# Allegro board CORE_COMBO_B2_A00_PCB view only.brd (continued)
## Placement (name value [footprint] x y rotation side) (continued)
RC58  -  [NB_R0402_SMALL]  129.1 73.4 270 top
RC59  -  [VX_R0402_SMALL]  157.14 77.72 180 top
RC64  -  [NB_R0402_SMALL]  128.21 73.4 270 top
RC65  -  [NB_R0402_SMALL]  127.32 73.4 270 top
RC66  -  [NB_R0402_SMALL]  130.49 73.4 270 top
RC67  -  [NB_R0402_SMALL]  131.13 37.07 90 top
RC68  -  [NB_R0402_SMALL]  131.13 38.73 90 top
RC69  -  [NB_R0402_SMALL]  130.24 38.73 90 top
RC70  -  [NB_R0402_SMALL]  132.17 70.73 90 top
RC79  -  [NB_R0402_SMALL]  128.71 74.74 0 bottom
RC80  -  [NB_R0402_SMALL]  88.58 101.21 0 bottom
RC82  -  [NB_R0402_SMALL]  133.03 75.93 90 top
RC83  -  [NB_R0402_SMALL]  134.94 39.11 0 top
RC84  -  [NB_R0402_SMALL]  73.21 127.37 270 bottom
RC88  -  [NB_R0402_SMALL]  128.74 75.93 270 top
RC89  -  [NB_R0402_SMALL]  127.9 75.93 270 top
RC90  -  [NB_R0402_SMALL]  99.16 98.28 270 top
RC91  -  [NB_R0402_SMALL]  98.33 98.27 270 top
RC95  -  [NB_R0402_SMALL]  65.19 113.63 180 bottom
RC96  -  [NB_R0402_SMALL]  133.67 90.41 0 top
RC98  -  [NB_R0402_SMALL]  133.03 72.61 270 top
RC101  -  [NB_R0402_SMALL]  58.3 112.61 90 bottom
RC113  -  [NB_R0402_SMALL]  88.58 100.32 0 bottom
RC114  -  [NB_R0402_SMALL]  101.89 98.18 90 top
RC117  -  [R0402]  90.15 105.2 90 bottom
RC126  -  [NB_R0402_SMALL]  131.63 25.39 90 top
RC128  -  [NB_R0402_SMALL]  135.57 25.77 0 top
RC130  -  [NB_R0402_SMALL]  128.59 25.39 0 top
RC132  -  [NB_R0402_SMALL]  130.36 25.39 90 top
RC133  -  [R0402]  80.73 127.12 0 bottom
RC134  -  [NB_R0402_SMALL]  100.19 109.82 270 top
RC137  -  [NB_R0402_SMALL]  149.92 89.65 0 bottom
RC140  -  [NB_R0402_SMALL]  154.24 84.57 270 bottom
RC147  -  [NB_R0402_SMALL]  102.45 112.21 90 top
RC149  -  [NB_R0402_SMALL]  103.41 116.17 270 top
RC153  -  [NB_R0402_SMALL]  101.41 112.21 90 top
RC155  -  [NB_R0402_SMALL]  102.25 116.17 270 top
RC156  -  [NB_R0402_SMALL]  147.89 96.66 0 bottom
RC158  -  [NB_R0402_SMALL]  132.52 95.49 180 top
RC169  -  [NB_R0402_SMALL]  155.59 76.52 90 top
RC172  -  [NB_R0402_SHORT]  90.87 101.21 180 bottom
RC186  -  [NB_R0402_SMALL]  143.95 93.69 180 bottom
RC189  -  [NB_R0402_SHORT]  106.59 37.96 180 top
RC190  -  [VX_R0402_SMALL]  157.07 81.41 180 top
RC191  -  [NB_R0402_SMALL]  56.7 123.94 0 bottom
RC192  -  [NB_R0402_SMALL]  143.95 92.65 180 bottom
RC193  -  [NB_R0402_SMALL]  149.92 90.54 0 bottom
RC198  -  [NB_R0402_SMALL]  131.51 75.93 270 top
RC199  -  [NB_R0402_SMALL]  154.62 87.87 0 bottom
RC224  -  [NB_R0402_SMALL]  136.97 112.54 90 bottom
RC227  -  [NB_R0402_SMALL]  139.13 112.38 180 bottom
RC228  -  [NB_R0402_SMALL]  139.25 113.27 0 bottom
RC244  -  [R0402_H16]  95.44 113.96 90 bottom
RC248  -  [R0402]  97.88 112.38 270 bottom
RC249  -  [NB_R0402_SMALL]  97.88 109.79 270 bottom
RC250  -  [NB_R0402_SMALL]  119.61 98.17 90 top
RC260  -  [NB_R0402_SMALL]  118.17 98.45 180 top
RC278  -  [R0402_H16]  88.76 102.14 0 bottom
RC297  -  [NB_R0402_SMALL]  104.48 112 90 top
RC298  -  [NB_R0402_SMALL]  105.29 112 90 top
RC305  -  [NB_R0402_SMALL]  145.22 110.1 90 bottom
RC306  -  [NB_R0402_SMALL]  144.38 110.1 90 bottom
RC309  -  [NB_R0402_SMALL]  185.3 126.1 180 bottom
RC314  -  [NB_R0402_SMALL]  139.71 109.36 90 bottom
RC317  -  [NB_R0402_SMALL]  37.45 128.49 180 bottom
RC318  -  [R0603_H24]  143.57 37.63 180 top
RC319  -  [R0603_H24]  146.37 29.83 180 top
RC324  -  [R0402]  111.85 97.91 270 top
RC338  -  [NB_R0402_SMALL]  141.92 88.63 180 bottom
RC339  -  [NB_R0402_SMALL]  143.57 89.27 0 bottom
RC340  -  [NB_R0402_SHORT_25MIL]  143.19 74.54 0 bottom
RC341  -  [NB_R0402_SMALL]  142.5 76.01 180 bottom
RC342  -  [VX_R0402_SMALL]  191.07 149.97 90 bottom
RC343  -  [NB_R0402_SMALL]  153.99 80.28 90 bottom
RC344  -  [NB_R0402_SMALL]  152.33 78.35 0 bottom
RC345  -  [NB_R0402_SMALL]  152.33 79.24 0 bottom
RC346  -  [NB_R0402_SMALL]  140.6 109.36 90 bottom
RC347  -  [VX_R0402_SMALL]  147.89 95.82 0 bottom
RC348  -  [NB_R0402_SMALL]  147.89 92.93 0 bottom
RC349  -  [NB_R0402_SMALL]  147.89 92.06 0 bottom
RC350  -  [VX_R0402_SMALL]  142.3 92.65 0 bottom
RC353  -  [NB_R0402_SMALL]  138.82 110.61 0 bottom
RC357  -  [NB_R0402_SMALL]  101.08 112.31 270 bottom
RC358  -  [NB_R0402_SMALL]  83.68 114.42 270 bottom
RC359  -  [NB_R0402_SMALL]  100.62 109.79 90 bottom
RC360  -  [NB_R0402_SMALL]  99.3 112.31 270 bottom
RC361  -  [NB_R0402_SMALL]  99.78 109.79 270 bottom
RC362  -  [NB_R0402_SMALL]  98.77 109.79 270 bottom
RC363  -  [NB_R0402_SMALL]  101.54 109.79 270 bottom
RC364  -  [NB_R0402_SMALL]  102.38 109.79 270 bottom
RC365  -  [NB_R0402_SMALL]  103.8 109.87 270 bottom
RC366  -  [NB_R0402_SMALL]  102.75 112.41 180 bottom
RC367  -  [NB_R0402_SMALL]  104 112.03 90 bottom
RC368  -  [NB_R0402_SMALL]  84.54 114.42 270 bottom
RC369  -  [NB_R0402_SMALL]  104.89 112.03 270 bottom
RC371  -  [NB_R0402_SMALL]  72.58 129.32 0 bottom
RC372  -  [NB_R0402_SMALL]  76.24 129.31 270 bottom
RC373  -  [NB_R0402_SMALL]  75.37 129.31 270 bottom
RC374  -  [NB_R0402_SMALL]  155.13 93.21 180 top
RC375  -  [NB_R0402_SMALL]  155.13 92.32 180 top
RC376  -  [NB_R0402_SMALL]  67.8 114.75 180 bottom
RC377  -  [NB_R0402_SMALL]  78.32 127.12 270 bottom
RC378  -  [NB_R0402_SMALL]  78.29 129.31 270 bottom
RC379  -  [NB_R0402_SMALL]  77.28 127.24 90 bottom
RC380  -  [NB_R0402_SMALL]  79.16 127.12 90 bottom
RC381  -  [NB_R0402_SMALL]  70.8 108.07 315 bottom
RC382  -  [NB_R0402_SMALL]  75.5 131.72 90 bottom
RC383  -  [NB_R0402_SMALL]  76.39 131.72 90 bottom
RC384  -  [NB_R0402_SMALL]  70.75 125.39 0 bottom
RC385  -  [NB_R0402_SMALL]  93.03 104 0 bottom
RC386  -  [R0402]  135.22 110.25 270 top
RC387  -  [NB_R0402_SMALL]  93.03 99.71 0 bottom
RC388  -  [NB_R0402_SMALL]  137.02 93.23 180 top
RC389  -  [NB_R0402_SMALL]  71.94 126.73 180 bottom
RC390  -  [NB_R0402_SMALL]  71.94 127.64 180 bottom
RC393  -  [NB_R0402_SMALL]  93.03 102.22 0 bottom
RC395  -  [NB_R0402_SMALL]  93.03 100.52 0 bottom
RC396  -  [NB_R0402_SMALL]  93.03 105.78 0 bottom
RC398  -  [NB_R0402_SMALL]  93.03 101.34 0 bottom
RC399  -  [NB_R0402_SMALL]  91.3 105.58 270 bottom
RC400  -  [NB_R0402_SMALL]  185.35 123.18 90 top
RC401  -  [NB_R0402_SMALL]  185.35 120.26 90 top
RC402  -  [NB_R0402_SMALL]  100.19 112.31 90 bottom
RC403  -  [NB_R0402_SMALL]  76.39 127.24 270 bottom
RC404  -  [NB_R0402_SMALL]  137.23 112.84 180 top
RC405  -  [NB_R0402_SMALL]  88.59 105.96 0 bottom
RC406  -  [NB_R0402_SMALL]  90.56 103.14 0 bottom
RC407  -  [NB_R0402_SMALL]  156.47 76.52 270 top
RC408  -  [NB_R0402_SMALL]  151.95 88.38 0 bottom
RC409  -  [NB_R0402_SMALL]  154.62 88.76 0 bottom
RC415  -  [NB_R0402_SMALL]  125.66 98.03 270 top
RC416  -  [NB_R0402_SMALL]  123.68 110.55 270 bottom
RC417  -  [NB_R0402_SMALL]  120.58 73.39 270 top
RC418  -  [NB_R0402_SMALL]  126.2 89.9 270 top
RC419  -  [R0603_H24]  156.53 110.61 270 top
RC420  -  [NB_R0402_SMALL]  121.68 74.03 90 top
RC421  -  [NB_R0402_SMALL]  123.13 74.03 270 top
RC422  -  [NB_R0402_SMALL]  97.9 109.82 270 top
RC423  -  [NB_R0402_SMALL]  98.97 109.82 270 top
RC424  -  [NB_R0402_SMALL]  130.39 88.71 90 top
RC425  -  [NB_R0402_SMALL]  135.32 91.58 180 top
RC426  -  [NB_R0402_SMALL]  135.32 92.47 180 top
RC427  -  [NB_R0402_SMALL]  138.87 98.29 180 top
RC428  -  [NB_R0402_SMALL]  137.25 91.2 0 top
RC429  -  [NB_R0402_SMALL]  152.33 90.03 180 top
RC430  -  [NB_R0402_SMALL]  139.3 93.13 270 top
RC431  -  [NB_R0402_SMALL]  140.14 93.13 270 top
RC432  -  [NB_R0402_SMALL]  138.42 93.13 270 top
RC433  -  [NB_R0402_SMALL]  131.99 68.23 90 top
RC434  -  [NB_R0402_SMALL]  147.76 58.15 180 top
RC435  -  [NB_R0402_SMALL]  145.29 114.29 270 top
RC436  -  [NB_R0402_SMALL]  142.17 114.39 270 top
RC437  -  [NB_R0402_SMALL]  144.46 114.29 270 top
RC438  -  [NB_R0402_SMALL]  133.08 111.16 270 bottom
RC439  -  [NB_R0402_SMALL]  146.35 114.29 270 top
RC440  -  [NB_R0402_SMALL]  139.66 94.73 180 top
RC442  -  [NB_R0805_H24_SMALL]  150.25 111.01 0 top
RC443  -  [NB_R0402_SMALL]  157.39 99.3 270 top
RC444  -  [NB_L0402_H22_SMALL]  141.29 114.39 270 top
RC445  -  [NB_L0402_H22_SMALL]  129.14 88.53 180 top
RC446  -  [NB_R0402_SMALL]  128.59 96.25 180 top
RC447  -  [R0603_H24]  126.63 94.42 180 top
RC448  -  [NB_R0402_SMALL]  93.03 97.24 0 bottom
RC449  -  [NB_R0402_SMALL]  93.03 98.9 180 bottom
RC450  -  [NB_R0402_SMALL]  133.08 112.81 90 bottom
RC451  -  [NB_R0402_SMALL]  143.06 114.29 270 top
RC452  -  [NB_R0402_SMALL]  141.92 91.63 0 bottom
RC453  -  [NB_R0402_SMALL]  120.53 75.38 90 top
RC454  -  [NB_R0402_SMALL]  128.43 97.79 0 top
RC455  -  [NB_R0402_SMALL]  86.55 102.22 0 bottom
RC456  -  [NB_R0402_SMALL]  182.21 93.97 180 top
RC457  -  [NB_R0402_SMALL]  182.21 94.86 180 top
RC458  -  [NB_R0402_SMALL]  189.42 91.94 0 top
RC460  -  [NB_R0402_SMALL]  154.62 85.84 180 bottom
RC461  -  [NB_R0402_SMALL]  152.33 86.48 180 bottom
RC462  -  [NB_R0402_SMALL]  152.33 85.59 180 bottom
RC463  -  [NB_R0402_SMALL]  154.62 86.98 180 bottom
RC464  -  [NB_R0402_SMALL]  54.8 123.94 0 bottom
RC465  -  [NB_R0402_SMALL]  54.8 124.83 0 bottom
RC466  -  [NB_R0402_SMALL]  138.82 109.36 90 bottom
RC467  -  [NB_R0402_SMALL]  141.49 109.36 90 bottom
RC468  -  [NB_R0402_SMALL]  147.89 91.17 0 bottom
RC469  -  [NB_R0402_SMALL]  154.62 86.86 180 top
RC471  -  [NB_R0402_H16_SMALL]  157.41 87.75 180 top
RC472  -  [NB_R0402_H16_SMALL]  157.41 86.86 180 top
RC473  -  [NB_R0402_SMALL]  157.29 83.17 180 top
RC474  -  [NB_R0402_SMALL]  157.29 84.06 180 top
RC475  -  [NB_R0402_SMALL]  152.33 80.28 0 bottom
RC476  -  [NB_R0402_SMALL]  134.1 109.67 90 bottom
RC477  -  [NB_R0402_SMALL]  154.62 87.75 180 top
RC478  -  [NB_R0402_SMALL]  152.33 87.75 0 top
RC479  -  [NB_R0402_SMALL]  155.26 95.93 0 bottom
RC480  -  [NB_R0402_SMALL]  134.3 95.49 0 top
RC481  -  [NB_R0402_SMALL]  134.99 109.67 90 bottom
RC486  -  [NB_R0402_SMALL]  229.88 64.5 90 top
RC487  -  [NB_R0402_SMALL]  133.95 70.73 270 top
RC488  -  [NB_R0402_SMALL]  133.06 70.73 90 top
RC491  -  [NB_R0402_SMALL]  136.08 112.54 270 bottom
RC582  -  [NB_R0402_SHORT]  151.96 92.83 180 bottom
RC584  -  [NB_R0402_SMALL]  53.15 123.94 0 bottom
RC585  -  [VX_R0402_SMALL]  156.75 78.58 180 top
RC586  -  [NB_R0402_SHORT]  151.95 91.68 180 bottom
RC587  -  [NB_R0402_SHORT]  152.03 94.53 90 bottom
RC590  -  [NB_R0402_SHORT]  151.95 90.54 180 bottom
RC591  -  [NB_R0402_SHORT]  130.02 75.15 90 bottom
RC593  -  [NB_R0402_SMALL]  136.46 90.29 0 top
RC594  -  [NB_R0402_SHORT]  138.74 113.11 270 top
RC595  -  [NB_R0402_SHORT]  124.52 71.49 90 top
RC600  -  [NB_R0402_SMALL]  65.19 112.71 180 bottom
RC604  -  [NB_R0402_SMALL]  26.35 115.43 270 bottom
RC605  -  [NB_R0402_SMALL]  27.37 115.43 270 bottom
RC606  -  [NB_R0402_SMALL]  28.38 115.43 270 bottom
RC607  -  [NB_R0402_SMALL]  29.25 115.43 270 bottom
RC608  -  [NB_R0402_SMALL]  152.33 82.03 0 bottom
RC609  -  [NB_R0402_SMALL]  141.92 89.65 0 bottom
RC610  -  [NB_R0402_SMALL]  152.33 89.14 0 top
RC611  -  [NB_R0402_SMALL]  155.41 81.06 180 top
RC612  -  [NB_R0402_SMALL]  155.41 81.93 180 top
RC613  -  [NB_R0402_SHORT]  151.96 89.4 180 bottom
RC615  -  [NB_R0402_SMALL]  139.66 95.59 180 top
RC616  -  [NB_R0402_SMALL]  139.71 96.84 180 top
RC617  -  [NB_R0402_SMALL]  165.85 61.53 0 top
RC618  -  [NB_R0402_SMALL]  134.72 75.93 270 top
RC619  -  [NB_R0402_SMALL]  131.38 73.14 270 top
RC620  -  [NB_R0402_SMALL]  143.57 110.1 270 bottom
RC621  -  [NB_R0402_SMALL]  177.23 49.39 0 top
RC622  -  [NB_R0402_SMALL]  150.96 95.87 270 bottom
RC623  -  [VX_R0402_SMALL]  190.18 149.98 90 bottom
RC624  -  [NB_R0402_SMALL]  123.76 68.21 0 top
RD3  -  [NB_R0402_SMALL]  104.96 38.72 270 top
RD4  -  [NB_R0402_SMALL]  114.67 29.02 90 top
RD14  -  [NB_R0402_SHORT_25MIL]  128.59 24.25 180 top
RD15  -  [NB_R0402_SHORT_25MIL]  129.17 38.39 90 top
RD61  -  [NB_R0402_SMALL]  115.12 38.47 270 top
RD62  -  [NB_R0402_SMALL]  146.11 35.93 90 top
RD63  -  [NB_R0402_SMALL]  148.78 35.93 90 top
RD64  -  [NB_R0402_SMALL]  125.79 38.47 90 top
RD66  -  [NB_R0402_SMALL]  147 35.93 270 top
RD67  -  [NB_R0402_SMALL]  147.89 35.93 270 top
RD68  -  [NB_R0402_SMALL]  124.9 38.47 270 top
RD69  -  [NB_R0402_SMALL]  147.25 28.06 270 top
RD70  -  [NB_R0402_SMALL]  148.78 30.6 0 top
RD71  -  [NB_R0402_SMALL]  122.74 25.77 0 top
RD72  -  [NB_R0402_SMALL]  145.98 28.06 90 top
RD73  -  [NB_R0402_SMALL]  150.43 30.47 90 top
RD74  -  [NB_R0402_SMALL]  123.63 24.88 0 top
RI27  -  [NB_R0402_SMALL]  104.43 128.24 180 top
RI28  -  [NB_R0402_SMALL]  104.43 129.05 180 top
RI29  -  [NB_R0402_SMALL]  104.43 130.22 180 top
RI30  -  [NB_R0402_SMALL]  104.43 131.03 180 top
RI31  -  [NB_R0402_SMALL]  98.87 123.31 0 bottom
RI32  -  [NB_R0402_SMALL]  98.84 134.63 0 bottom
RI33  -  [NB_R0402_SMALL]  105.98 138.42 90 top
RN25  -  [NB_R0402_SMALL]  173.29 52.57 180 top
RN31  -  [NB_R0402_SMALL]  173.29 49.52 180 top
RN246  -  [2R4P0603_H28]  21.78 93.97 90 top
RN247  -  [2R4P0603_H28]  156.12 135.19 180 bottom
RN248  -  [2R4P0603_H28]  21.78 96.25 90 top
RN249  -  [2R4P0603_H28]  19.35 96.1 270 bottom
RN483  -  [2R4P0603_H28]  110.55 123.66 90 bottom
RN2728  -  [2R4P0603_H28]  189.71 121.54 0 bottom
RN3601  -  [2R4P0603_H28]  206.97 145.81 180 top
RN4100  -  [2R4P0603_H28]  27.62 101.46 0 bottom
RN4101  -  [2R4P0603_H28]  17.44 115.05 90 top
RN4102  -  [2R4P0603_H28]  17.44 117.59 90 top
RN4103  -  [2R4P0603_H28]  17.44 112.54 90 top
RN4104  -  [2R4P0603_H28]  17.44 109.97 90 top
RN4105  -  [2R4P0603_H28]  180.15 42.21 0 bottom
RN4106  -  [2R4P0603_H28]  21.39 134.18 90 bottom
RN4107  -  [NB_R0402_SMALL]  171.64 61.2 0 top
RN4108  -  [NB_R0402_SMALL]  173.29 51.55 180 top
RN4109  -  [NB_R0402_SMALL]  173.29 47.49 180 top
RN4110  -  [NB_R0402_SMALL]  173.29 50.53 180 top
RN4111  -  [NB_R0402_SMALL]  171.64 52.57 180 top
RN4112  -  [NB_R0402_SMALL]  171.64 51.55 180 top
RN4113  -  [NB_R0402_SMALL]  171.64 47.49 180 top
RN4114  -  [NB_R0402_SMALL]  171.64 50.53 180 top
RN4115  -  [NB_R0402_SMALL]  161.35 51.68 0 top
RN4116  -  [NB_R0402_SMALL]  161.35 50.79 0 top
RN4117  -  [NB_R0402_SMALL]  161.35 49.01 0 top
RN4119  -  [NB_R0402_SMALL]  163 51.68 0 top
RN4120  -  [NB_R0402_SMALL]  163 50.79 0 top
RN4121  -  [NB_R0402_SMALL]  163 49.01 0 top
RN4122  -  [NB_R0402_SMALL]  173.29 48.5 180 top
RN4123  -  [NB_R0402_SMALL]  161.35 49.9 0 top
RN4124  -  [NB_R0402_SMALL]  161.35 48.12 0 top
RN4125  -  [NB_R0402_SMALL]  171.64 48.5 180 top
RN4126  -  [NB_R0402_SMALL]  163 49.9 0 top
RN4127  -  [NB_R0402_SMALL]  163 48.12 0 top
RN4128  -  [NB_R0402_SMALL]  173.29 64.25 180 top
RN4129  -  [NB_R0402_SMALL]  173.29 63.23 180 top
RN4130  -  [NB_R0402_SMALL]  173.29 59.17 180 top
RN4131  -  [NB_R0402_SMALL]  173.29 62.22 180 top
RN4132  -  [NB_R0402_SMALL]  171.64 64.25 180 top
RN4133  -  [NB_R0402_SMALL]  171.64 63.23 180 top
RN4134  -  [NB_R0402_SMALL]  171.64 59.17 180 top
RN4135  -  [NB_R0402_SMALL]  171.64 62.22 180 top
RN4136  -  [NB_R0402_SMALL]  161.38 63.23 0 top
RN4137  -  [NB_R0402_SMALL]  161.38 62.35 0 top
RN4138  -  [NB_R0402_SMALL]  161.38 60.44 0 top
RN4139  -  [NB_R0402_SMALL]  163 63.23 0 top
RN4140  -  [NB_R0402_SMALL]  163 62.35 0 top
RN4141  -  [NB_R0402_SMALL]  163 60.44 0 top
RN4142  -  [NB_R0402_SMALL]  173.29 60.19 180 top
RN4143  -  [NB_R0402_SMALL]  161.38 61.33 0 top
RN4144  -  [NB_R0402_SMALL]  161.38 59.55 0 top
RN4145  -  [NB_R0402_SMALL]  171.64 60.19 180 top
RN4146  -  [NB_R0402_SMALL]  163 61.33 0 top
RN4147  -  [NB_R0402_SMALL]  163 59.55 0 top
RN4149  -  [2R4P0603_H28]  184.34 53.71 180 bottom
RN4150  -  [2R4P0603_H28]  168.09 93.46 0 bottom
RN4151  -  [2R4P0603_H28]  168.09 88.63 0 bottom
RN4152  -  [2R4P0603_H28]  168.21 83.68 0 bottom
RP2  -  [4R8P_H24]  222.29 63.13 90 top
RP6  -  [4R8P0402_H20]  91.98 119.95 180 top
RP8  -  [4R8P0402_H20]  152.59 92.45 270 top
RP9  -  [4R8P0402_H20]  152.33 83.81 90 bottom
RP10  -  [4R8P0402_H20]  132.52 110.48 0 top
RP4804  -  [8R10P]  255.97 39.49 180 top
RP4806  -  [8R10P]  264.6 25.52 0 top
RP4807  -  [4R8P0402_H20]  268.54 52.19 270 top
RP4808  -  [4R8P0402_H20]  136.74 75.3 0 bottom
RP4810  -  [4R8P0402_H20]  268.29 62.35 0 top
RP4811  -  [4R8P0402_H20]  265.75 62.35 0 top
RTCD1  -  [SOT323_ONSEMI]  75.25 27.55 180 top
RTCR1  -  [NB_R0402_SMALL]  75.5 30.09 0 top
SW5  -  [SW_4P_189X189]  188.66 143.37 0 top
T92  -  [NB_TPC26T_68]  145.48 138.57 180 top
T93  -  [NB_TPC26T_68]  143.88 139.23 180 top
T2703  -  [NB_TPC26T_68]  37.93 126.73 270 top
T2704  -  [NB_TPC26T_68]  43.09 129.07 0 top
T2705  -  [NB_TPC26T_68]  42.99 131.15 0 top
T2706  -  [NB_TPC26T_68]  44.97 129.66 0 top
T2707  -  [NB_TPC26T_68]  44.13 129.27 180 bottom
T6203  -  [NB_TPC26T_68]  109.74 102.45 0 top
T6204  -  [NB_TPC26T_68]  110.81 101.08 0 top
T6207  -  [NB_TPC26T_68]  105.83 77.08 90 top
T6208  -  [NB_TPC26T_68]  105.8 78.86 90 top
T6209  -  [NB_TPC26T_68]  107.12 86.09 90 top
T6210  -  [NB_TPC26T_68]  107.96 84.16 0 top
T6211  -  [NB_TPC26T_68]  92.54 80.99 180 bottom
T6212  -  [NB_TPC26T_68]  124.34 45.94 0 top
T6213  -  [NB_TPC26T_68]  124.78 41.52 0 top
T6215  -  [NB_TPC26T_68]  124.06 30.34 0 top
T6216  -  [NB_TPC26T_68]  124.01 28.56 0 top
T6217  -  [NB_TPC26T_68]  124.14 101.11 0 top
T6218  -  [NB_TPC26T_68]  126.07 101.21 0 top
T6219  -  [NB_TPC26T_68]  123.73 107.18 90 top
T6220  -  [NB_TPC26T_68]  124.83 105.75 90 top
T6249  -  [NB_TPC26T_68]  257.11 27.93 180 bottom
T6256  -  [NB_TPC26T_68]  259.09 27.47 180 bottom
T6263  -  [NB_TPC26T_68]  257.01 30.42 180 bottom
T6265  -  [NB_TPC26T_68]  258.28 31.69 180 bottom
T6266  -  [NB_TPC26T_68]  260.06 31.42 180 bottom
T6271  -  [NB_TPC26T_68]  269.96 35.65 180 top
T6272  -  [NB_TPC26T_68]  265.33 36.97 180 bottom
T6273  -  [NB_TPC26T_68]  267.27 36.97 180 bottom
T6294  -  [NB_TPC26T_68]  88.4 118.53 90 top
T6295  -  [NB_TPC26T_68]  86.69 118.8 90 top
T6296  -  [NB_TPC26T_68]  88.94 121.48 90 top
T6297  -  [NB_TPC26T_68]  88.02 122.97 90 top
T6298  -  [NB_TPC26T_68]  87.59 120.33 90 top
T6299  -  [NB_TPC26T_68]  85.82 120.34 0 top
T6300  -  [NB_TPC26T_68]  83.78 120.03 0 top
T6301  -  [NB_TPC26T_68]  83.78 121.78 0 top
T6302  -  [NB_TPC26T_68]  80.85 123.76 270 top
T6303  -  [NB_TPC26T_68]  85.13 122.95 0 top
T6304  -  [NB_TPC26T_68]  84.69 118.53 0 top
T6305  -  [NB_TPC26T_68]  82.05 120.71 0 top
T6306  -  [NB_TPC26T_68]  82.03 122.47 0 top
T6340  -  [NB_TPC26T_68]  102.73 132.7 90 top
T6353  -  [NB_TPC26T_68]  102.04 130.93 90 top
T6354  -  [NB_TPC26T_68]  266.76 31.28 180 bottom
T7101  -  [NB_TPC26T_68]  256.09 100.06 0 top
T7108  -  [NB_TPC26T_68]  97.5 76.21 180 bottom
T7109  -  [NB_TPC26T_68]  95.72 74.28 180 bottom
T7110  -  [NB_TPC26T_68]  129.94 84.83 0 top
T7111  -  [NB_TPC26T_68]  132.9 86.98 0 top
T7112  -  [NB_TPC26T_68]  135.44 82.51 0 top
T7113  -  [NB_TPC26T_68]  135.57 84.32 0 top
T7114  -  [NB_TPC26T_68]  136.61 81.12 0 top
T7115  -  [NB_TPC26T_68]  140.02 82.03 0 top
T7116  -  [NB_TPC26T_68]  138.14 82.03 0 top
T7117  -  [NB_TPC26T_68]  93.53 79.39 180 bottom
T7118  -  [NB_TPC26T_68]  91.53 79.39 180 bottom
T7119  -  [NB_TPC26T_68]  90.51 77.56 180 bottom
T7120  -  [NB_TPC26T_68]  95.67 76.9 180 bottom
T7121  -  [NB_TPC26T_68]  85.43 131.98 90 bottom
T7122  -  [NB_TPC26T_68]  104.56 83.43 0 top
T7123  -  [NB_TPC26T_68]  105.95 82.33 0 top
T7136  -  [NB_TPC26T_68]  106.79 103.26 0 top
T7137  -  [NB_TPC26T_68]  104.99 101.66 0 top
T7138  -  [NB_TPC26T_68]  89.14 103.75 180 bottom
T7139  -  [NB_TPC26T_68]  131.25 82.03 0 top
T7140  -  [NB_TPC26T_68]  95.57 105.88 180 bottom
T7141  -  [NB_TPC26T_68]  113.85 101.13 0 top
T7142  -  [NB_TPC26T_68]  108.01 88.25 0 top
T7149  -  [NB_TPC26T_68]  139.38 80 0 top
T7150  -  [NB_TPC26T_68]  137.86 86.02 0 top
T7157  -  [NB_TPC26T_68]  110.6 128.66 180 bottom
T7158  -  [NB_TPC26T_68]  108.11 137.05 0 top
T7159  -  [NB_TPC26T_68]  110.93 144.74 180 bottom
T7160  -  [NB_TPC26T_68]  107.66 143.78 180 bottom
T7161  -  [NB_TPC26T_68]  25.44 137.02 0 top
T7162  -  [NB_TPC26T_68]  25.08 120 0 top
T7163  -  [NB_TPC26T_68]  115.91 144.87 180 bottom
T7164  -  [NB_TPC26T_68]  260.16 61.46 0 top
U1  -  [SOIC_8P_50_213X311]  157.48 114.9 180 bottom
U2  -  [SOIC_8P_50_213X311]  148.65 114.16 180 bottom
U5  -  [SOT353_PHILIPS]  81.47 33.9 180 top
U6  -  [BGA_168P_26_335X394]  88.23 129.36 180 top
U7  -  [SOIC_8P_50_197X236_IDT]  76.01 142.61 270 top
U9  -  [NB_SOT23_S6_FITI_H57]  51.93 94.15 270 bottom
U15  -  [LGA_12P_20_79X79_ST]  190.94 48.76 90 bottom
U17  -  [QFN_48P_16_S236_PAD_REA_9V]  41.72 122.67 90 top
U18  -  [SON_14P_16_118X79_PAD]  51.24 129.4 270 bottom
U21  -  [QFN_48P_16_S236_PAD_IE_4V]  145.55 132.14 0 top
U22  -  [SOT26_H55]  187.51 137.91 270 top
U24  -  [SC70_S5]  159.83 137.11 270 top
U25  -  [QFN_32P_20_197X197_PAD_RIC]  190.31 145.53 0 bottom
U26  -  [QFN_32P_20_S197_PAD_NAT]  270.32 41.52 0 top
U32  -  [DFN_8P_20_S79_PAD_INTER_H31]  198.69 42.91 0 bottom
U37  -  [DRQFN_132P_20_S433_PAD_9V]  260.28 53.58 0 top
U38  -  [DRQFN_132P_20_S433_PAD_9V]  234 56.63 0 top
U43  -  [SON_14P_16_118X79_PAD]  185.61 97.52 90 top
U45  -  [SON_14P_16_118X79_PAD]  185.61 87.36 90 top
U46  -  [SON_14P_16_118X79_PAD]  207.33 60.19 0 top
U51  -  [SON_14P_16_118X79_PAD]  56.45 121.15 0 bottom
U92  -  [QFN_36P_20_S236_PAD_SSC_8V]  185.1 131.18 90 bottom
U6202  -  [QFN_64P_20_S354_PAD_SL_8V]  263.97 32.63 180 top
U6203  -  [SOIC_28P_26_386X252]  126.48 141.31 180 top
U6204  -  [QFN_16P_20_S118_PAD_RIC_H31]  23.05 96 270 bottom
U6205  -  [QFN_24P_20_S157_PAD_H31_4V]  167.32 50.15 0 bottom
U6206  -  [QFN_24P_20_S157_PAD_H31_4V]  167.3 61.76 0 bottom
U6207  -  [SOT363_PHILIPS]  47.58 88.32 90 top
U6217  -  [SON_14P_16_118X79_PAD]  185.61 91.56 90 top
U6218  -  [SOT353_PHILIPS]  218.63 68.19 270 top
U6220  -  [DFN_10P_20_98X39_NXP]  252.77 99.78 90 top
U6221  -  [DFN_8P_26_118X118_P_TI]  90.74 111.75 270 top
U6222  -  [DFN_8P_26_118X118_P_TI]  119.47 67.09 90 top
U6223  -  [SOT363_PHILIPS]  52.46 88 270 bottom
UC1  -  [BGA_1356P_1654X945_INTEL]  117.53 91.4 0 bottom
UC3  -  [SC70_S5]  153.1 81.27 270 top
UC6  -  [QFN_14P_20_118X98_PAD]  61.77 112.08 270 bottom
UC8  -  [SC70_S5]  135.82 114.75 270 bottom
UC9  -  [SC70_S5]  155.68 90.29 0 top
UC10  -  [SC70_S5]  189.73 99.56 180 top
UC11  -  [SC70_S5]  222.31 68.27 270 top
UC12  -  [SC70_S5]  57.63 114.29 90 top
UC13  -  [SC70_S5]  250.33 45.03 0 top
UC14  -  [SC70_S5]  124.47 66.38 90 top
US2  -  [SOIC_8P_26_122X193]  144.31 137.12 90 bottom
X1  -  [XTAL_4P_126X98_HELE]  145.48 122.92 270 top
Y1  -  [XTAL_4P_126X98_RAK]  78.04 135.37 270 top
Y4  -  [XTAL_2P_126X59]  224.47 52.95 270 top
Y8  -  [XTAL_4P_126X98_HELE_H31]  185.18 122.92 180 bottom
YC2  -  [VX_XTAL_4P_126X98_HELE]  118.7 112.74 180 bottom
YC3  -  [XTAL_4P_272X55]  150.08 75.5 0 bottom

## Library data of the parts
C4 C9 C19 C20 C22 C27 C34 C54-C57 C59-C64 C68 C87 C103 C112-C115 C117 C119 C120 C123 C129 C133 C135 C137 C143 C155-C162 C176 C178 C179 C181 C183-C186 C191 C198 C199 C208 C209 C242 C243 C257 C260 C261 C269-C272 C289 C291-C293 C329-C334 C345 C346 C349-C351 C353-C356 C360 C367 C371 C374-C376 C440 C633-C635 C645 C647 C648 C1002 C1103 C1104 C1186 C1187 C1189 C2800-C2803 C3005 C3050 C3051 C3054-C3059 C3062 C3063 C3079 C3082 C3083 C3085 C3086 C3402 C3601-C3603 C3701 C9207 C9437 C9441-C9450 C9457-C9459 C9462-C9464 C9525-C9528 C9548-C9552 C9555-C9557 C9559 C9560 C9562 C9564 C9566-C9568 C9642 C9644 C9851 C9855 C9856 C9884 C9886 C9887 C9903 C9905 C9918-C9922 C9929 C9931 C9942 C9946-C9949 C9953-C9955 C9959 C9960 C9982 C9984 C9985 CC10 CC11 CC41 CC93 CC94 CC267 CC268 CC272 CC273 CD3 CD13 CD23 CD24 CD34 CD60 CD132 CE14 CE22 CZ58 CZ59 = DEV_288
C7 = DEV_281
C8 C9952 PC5507 PC5508 = DEV_257: room: 1.05VS
C10-C15 = DEV_362
C16 C370 C373 C9461 = DEV_131
C17 C18 C139 C2750 C9914-C9917 C9941 CE1 CE2 = DEV_122
C21 C26 C3087 C3092 C9515 C9516 C9943 = DEV_279
C23 C24 C28 C29 C3084 C3088 C3091 C3093 C3094 C9553 C9554 C9944 C9945 CC266 CS1-CS4 = DEV_350
C25 C50 C134 C149 C151 C182 C263 C340 C342-C344 C347 C352 C362 C389 C393 C396 C399 C400 C403 C410 C422 C425 C426 C430 C452 C3060 C3061 C9451 C9842 C9843 C9885 C9900 C9950 CC24 CC26 CC269 CD4-CD11 CD26-CD29 CD36-CD43 CD54-CD57 CD62-CD70 CD85 CD86 CD93 CD95-CD100 CD134 CD135 = DEV_285
C42 C43 CC89-CC92 = DEV_135
C52 C65 C9438-C9440 C9930 = DEV_282
C66 C111 C124 C125 C147 C390 C402 C3004 C7108-C7111 C9539-C9541 C9841 C9907-C9911 C9913 C9923 C9925-C9928 C9986 PC5902 PC5910 PC5916 = DEV_136
C76 C85 C250 C252 C266 C339 C9957 C9962 C9966 C9968 C9970 C9972 C9974 C9976 C9978 = DEV_37
C88 C122 C128 C180 C288 C328 C348 C385 C3053 C3401 C9432 C9563 C9565 C9569 C9606 C9613 C9614 C9618 C9620-C9622 C9654 C9655 C9888 C9889 C9956 C9958 C9981 CD14-CD21 CD30 CD31 CD45-CD52 CD58 CD59 CD71-CD78 CD89 CD90 CD101-CD108 CD136 CD137 = DEV_286
C118 C150 C262 C336 C366 C3052 C9558 C9897-C9899 C9904 = DEV_287
C131 = DEV_42
C136 C377-C380 C9513 C9514 CC6 CC7 = DEV_157
C148 C391 C397 C398 C401 C409 C413 C427 C9492-C9495 C9505-C9507 C9840 C9912 C9924 CC270 CC271 CC275-CC282 CC284-CC286 CC288 PC5104 = DEV_134
C187 C188 C251 C9619 C9623 C9624 C9629 C9632 C9647-C9649 C9656 = DEV_284
C189 C190 C364 C365 CC5 CC25 CC57 CC80 CC287 CC290 = DEV_38
C248 C249 C258 C259 C337 C9455 = DEV_156
C253 C254 C290 = DEV_56
C358 C359 C361 C9460 C9961 C9965 C9967 C9969 C9971 C9973 C9975 C9977 = DEV_132
C363 = DEV_155
C368 C369 = DEV_133
C395 C9964 C9980 = DEV_121
C431 PC5304 PC5318 PC5408 PC5409 = DEV_162
C809 = DEV_55
C2805 = DEV_283
C3080 = DEV_332
C7106 C7112 = DEV_338
C9430 PR5312 R474 RC56 RC57 = DEV_111
C9433 = DEV_47
C9453 C9454 C9456 = DEV_280
C9491 = DEV_90
C9508 C9542-C9544 = DEV_196
C9509-C9512 = DEV_195
C9607-C9612 C9615-C9617 C9625-C9628 C9630 C9631 C9633-C9641 C9643 C9645 C9650 C9653 C9657-C9660 C9663-C9666 C9906 C9983 = DEV_166
C9901 CD12 CD25 CD61 CD133 = DEV_278
C9963 C9979 PC5210 = DEV_263: room: CHG
CC67 CC69 = DEV_43
CC289 = DEV_277
CD22 CD53 = DEV_36
CMOS1 JTAG1 ME1 = DEV_11
CRTF1 FANF1 = DEV_89
CU16-CU23 CU31-CU36 CU41-CU50 = DEV_276
D1 D12 D14 D23 D24 D7110-D7112 = DEV_35
D2 D21 D7123 RTCD1 = DEV_174
D4 D66 D2800 D2801 = DEV_304
D17 D2301 D2302 = DEV_359
D22 D25 D67 D69 D7113 D7119-D7122 = DEV_305
D64 D65 = DEV_45
D68 = DEV_275
D2700 = DEV_314
D7101-D7103 D7117 D7118 = DEV_325
D7108 D7109 PD5101-PD5103 = DEV_185
H1-H3 H5-H10 H12 = DEV_76
H2_2 H3_2 H24 = DEV_84
H5_2 = DEV_178
H11 = DEV_183
H13 H14 = DEV_88
H15 H16 = DEV_80
H17 = DEV_179
H18 = DEV_81
H19 = DEV_180
H20-H23 = DEV_186
H25 = DEV_328
H7101 H7102 = DEV_324
H7301 H7302 = DEV_154
HDMIU1 = DEV_54
JAPS1 = DEV_100
JBAT1 JBAT_PK1 = DEV_274
JBAT_PK2 = DEV_152
JCRT1 = DEV_188
JCSW1 JLID1 = DEV_65
JCSW2 = DEV_79
JDCIN1 = DEV_171
JDEG1 = DEV_380
JDEG2 = DEV_337
JDIMM1 = DEV_273
JDIMM2 = DEV_272
JDOCK1 JIOR1 = DEV_271
JEDP1 = DEV_68
JEPC1 = DEV_74
JFAN1 JSPK1 = DEV_64
JFWP1 = DEV_270
JGFX1 = DEV_102
JGPS1 = DEV_67
JHDMI1 = DEV_95
JHS1 = DEV_365
JKB1 = DEV_98
JLAN1 = DEV_184
JLED1 = DEV_336
JODD1 JSH1 = DEV_50
JPSEN1 = DEV_91
JRCAM1 = DEV_75
JRTC1 = DEV_73
JSEC1 = DEV_269
JSER1 = DEV_97
JSIM1 = DEV_323
JSIMUAJ1 = DEV_129
JSIMUAJ2 = DEV_322
JSPI1 = DEV_268
JSTRG1 = DEV_267
JTP1 = DEV_78
JUAJ1 = DEV_326
JUSB1 = DEV_82
JUSB2 = DEV_96
JWLAN1 = DEV_72
JWWAN1 = DEV_71
JXDP1 = DEV_33
L1-L3 = DEV_361
L4 L5 = DEV_53
L8 L10 L13 L16 L19 L40-L42 L57 L75 L3101 L3601 L3602 L7103-L7106 = DEV_32
L21 = DEV_44
L27 = DEV_306
L37 PC7407 R9629 RC318 RC319 RC419 RC447 = DEV_164
L44 L45 L2701 L2702 R181 R9535 = DEV_128
L76 = DEV_354
L77-L80 L7107 L7108 = DEV_358
L2800 = DEV_194
L7101 L7102 = DEV_321
LE1 = DEV_127
OCS4801 = DEV_177
PC5101 PC5103 PC5105-PC5107 PC5502 = DEV_130
PC5102 PC5303 PC5309 PC5404 PC5505 PC5603 PC5615 PC5808 PC5836 = DEV_132: room: CHG
PC5108 = DEV_266
PC5109 = DEV_126
PC5201 PC5225 PC5227 PC5239 = DEV_265: room: CHG
PC5202 PC5203 PC5232 PC5235 PC5236 = DEV_264: room: CHG
PC5204-PC5208 PC5211 PC5215-PC5221 PC5223 = DEV_158: room: SYS
PC5209 PC5212 PC5213 PC5908 PC5921 PC5922 PC5931 PC5932 = DEV_187
PC5214 = DEV_264
PC5222 PC5224 PC5234 PC5237 PC5240 PC5241 PC5413 = DEV_131: room: CHG
PC5226 = DEV_262: room: CHG
PC5228-PC5231 = DEV_77: room: SYS
PC5233 = DEV_261: room: CHG
PC5238 PC5802 PC5809 PC5826 PC5839 = DEV_260: room: COR
PC5301 PC5302 PC5306 PC5307 PC5320 PC5321 PC5911 PC5913 PC7401 = DEV_320: room: COR
PC5305 PC5310 PC5311 PC7404 = DEV_130: room: SYS
PC5308 PC5414 PC5415 PC5504 = DEV_260
PC5312 PC5313 = DEV_62
PC5314 PC5315 PC5412 PC5914 PC5924 PC5928 = DEV_125: room: SYS
PC5316 PC5317 PC7405 = DEV_124: room: SYS
PC5319 = DEV_379
PC5401 PC5402 PC5406 PC5407 = DEV_266: room: DDR
PC5403 = DEV_260: room: CHG
PC5405 = DEV_259
PC5410 = DEV_161
PC5411 = DEV_160
PC5416 PC5702 PC5703 PC5711 PC5712 PC5720 PC5721 PC5725 PC5736 PC5739 = DEV_255: room: 1.5V&1.8V
PC5501 PC5503 PC5903-PC5906 PC5917-PC5920 = DEV_266: room: COR
PC5506 = DEV_313: room: 1.05VS
PC5509 PC5510 PC6001 PC6003-PC6027 PC6029 PC6035 PC6038 PC6040-PC6053 PC6056-PC6075 PC6123 PC6125 PC6126 PC6130 PC6132 PC6133 PC6136 PC6137 PC6139 PC6140 PC6143-PC6147 PC7403 PC7409 = DEV_303: room: 1.05VS
PC5511 = DEV_125: room: 1.05VS
PC5512 PC5513 = DEV_256
PC5514 PC5610 PC5620 PC7406 = DEV_260: room: 1.05VS
PC5601 PC5609 PC5611 PC5619 = DEV_134: room: COR
PC5602 PC5612 = DEV_159
PC5604 PC5605 PC5616 PC5618 = DEV_255: room: COR
PC5606-PC5608 PC5613 PC5614 PC5617 PC5705 PC5707 PC5713 PC5714 PC5723 PC5724 PC5732 PC5734 PC5737 PC5738 = DEV_303: room: 1.5V&1.8V
PC5701 PC5704 PC5706 PC5710 PC5715 PC5716 PC5719 PC5722 PC5726 PC5727 PC5731 PC5735 = DEV_254: room: 1.5V&1.8V
PC5708 PC5717 PC5729 PC5733 = DEV_196: room: 1.5V&1.8V
PC5709 PC5718 PC5728 PC5730 = DEV_125: room: 1.5V&1.8V
PC5801 PC5828 = DEV_258: room: CHG
PC5803 = DEV_265: room: COR
PC5804 = DEV_341: room: COR
PC5805 PC5835 = DEV_196: room: CHG
PC5806 PC5818 PC5823 PC5834 PC5838 = DEV_132: room: COR
PC5807 PC5827 PC5831 = DEV_331: room: COR
PC5810 = DEV_353: room: COR
PC5812 = DEV_157: room: COR
PC5813 PC5814 PC5816 = DEV_251: room: COR
PC5815 PC5821 PC5822 PC5840 PC5841 = DEV_258: room: COR
PC5817 = DEV_252: room: COR
PC5819 PC5824 = DEV_253: room: COR
PC5820 PC5825 PC5842 = DEV_315: room: COR
PC5830 PC5832 = DEV_319: room: COR
PC5837 = DEV_136: room: CHG
PC5843 = DEV_121: room: COR
PC5901 PC5915 PC5925 = DEV_250: room: COR
PC5909 PC5923 PC5926 = DEV_340: room: SYS
PC5912 PC5927 PC5929 PC5930 = DEV_123
PC6076-PC6122 PC6127-PC6129 PC6131 PC6134 PC6135 PC6138 PC6141 PC6142 = DEV_249: room: 1.05VS
PD5201 PD5202 PD5205 = DEV_34
PD5206 = DEV_190
PH5801 PH5804 = DEV_302
PH5802 PH5803 PH5805 = DEV_61
PJP6 PJP7 = DEV_14
PJP10 PJP802 PJP803 PJP805 PJP3301 PJP5306 PJP5307 PJP5402 PJP5403 PJP5601 PJP5603 PJP5701-PJP5708 PJP5806 PJP5809 PJP5811-PJP5813 PJP5815 PJP5909 PJP5912 PJP5913 = DEV_14: room: SYS
PJP5201-PJP5204 = DEV_12: room: CHG
PJP5301 PJP5302 PJP5308 PJP5401 PJP5404 PJP5501 PJP5502 PJP5810 PJP5911 = DEV_15: room: DDR
PJP5303-PJP5305 = DEV_12: room: SYS
PJP5602 PJP5604 PJP5908 = DEV_13: room: SYS
PJP5901-PJP5906 = DEV_12: room: COR
PL5101 PL5102 PL5104 PL5201 PL5302 PL5303 PL5401 PL5501 PL5902-PL5904 = DEV_248
PL5103 = DEV_357
PL5202 = DEV_83
PL5301 = DEV_309
PL5304 = DEV_63
PL5402 = DEV_247
PL5502 = DEV_31
PL5601 PL5602 = DEV_246
PL5701-PL5703 = DEV_308
PL5704 = DEV_364
PL5901 PL5906 = DEV_245
PL5905 = DEV_327
PL7401 = DEV_374
PQ5101 = DEV_27
PQ5102 Q11 Q12 Q14 Q3603 = DEV_30
PQ5103 = DEV_26
PQ5104 = DEV_193
PQ5105 PQ5203-PQ5207 PQ5213 = DEV_25
PQ5106 PQ5202 PQ5210 PQ5214 PQ5220 Q5 Q17 Q19 Q22 Q23 Q25 Q28 Q30 Q32 Q33 Q122 Q3602 Q3605 Q4209 QC1 QC2807 QC2808 QZ22 U6207 U6223 = DEV_58
PQ5201 PQ5208 = DEV_165
PQ5209 PQ5211 PQ5212 PQ5215-PQ5217 Q4 Q217 Q1701 Q3606 Q3607 Q4200 Q4203 Q4215 = DEV_101
PQ5218 = DEV_349
PQ5219 = DEV_29
PQ5301 PQ5902 = DEV_243
PQ5302 PQ5401 = DEV_244
PR5101 PR5103 PR5104 PR5236 PR5604 PR5805 PR5806 R384 R803 R9531 RC250 RC361 RC367 RC420 RC422 RC448 RC486 = DEV_119
PR5102 PR5113 PR5116 PR5118 PR5240 PR5250 PR5255 PR5262 PR5304 PR6091 PR7405 R28 R36 R96 R97 R125 R126 R163 R208 R226 R227 R229 R268 R282 R286 R288 R298 R302 R309 R322 R327 R328 R343 R344 R346 R347 R360 R362 R364 R368 R370-R372 R380 R391 R398 R419 R432 R2672 R2677 R2721 R2729 R2730 R2732 R4104 R7101 R9394 R9398-R9400 R9403-R9408 R9415 R9417 R9418 R9421 R9452-R9454 R9461 R9485 R9489 R9493 R9497 R9500 R9532 R9543 R9546 R9583 R9587-R9589 R9591 R9627 R9673 R9688 R9691 R9692 RC11 RC147 RC149 RC153 RC155 RC156 RC158 RC191 RC198 RC199 RC407 RC480 RC584 RC617 = DEV_120
PR5105 R55 R65 R196 R216 R217 R339 R345 R348 R350 R359 R361 R403 R454 R455 R470 R471 R731 R732 R2736 R9537-R9539 R9545 R9570 R9623 R9624 R9636 R9637 R9677-R9680 = DEV_117
PR5106 R136 R149 R324 RC23-RC26 = DEV_116
PR5107 PR5207 PR5209 PR5221 PR5260 = DEV_120: room: CHG
PR5108 PR5109 PR5308 PR5508 PR5813 PR5840 R35 R64 R122-R124 R171 R172 R182 R292 R310 R329 R330 R340 R354 R366 R373 R376 R377 R393 R395-R397 R399 R408 R428 R460 R473 R478 R479 R713 R2722 R2724-R2727 R3702 R3703 R7102 R9395 R9396 R9416 R9427-R9431 R9444 R9446 R9462 R9463 R9466 R9526 R9527 R9529 R9534 R9592 R9631 R9638 R9668 R9684 R9690 RC70 RC98 RC137 RC140 RC169 RC193 RC305 RC306 RC314 RC343-RC346 RC353 RC374 RC383-RC385 RC408 RC409 RC466-RC468 RC475-RC479 RC481 RC487 RC488 RC608-RC610 RC620 RC621 RN25 RN4108-RN4117 RN4119-RN4147 = DEV_115
PR5110 PR5309 = DEV_114
PR5112 PR5114 PR5115 PR5206 PR5263 R44 R47 R66 R98 R195 R475 R9542 R9544 R9557 R9594 RC44 RC309 RC317 = DEV_113
PR5117 PR5204 PR5211 PR5214 PR5216 PR5218 PR5242 PR5244 PR5245 PR5259 = DEV_115: room: CHG
PR5201 PR5210 = DEV_181: room: CHG
PR5202 PR5233 = DEV_169: room: CHG
PR5203 PR5213 = DEV_182: room: CHG
PR5205 PR5208 PR5215 PR5219 = DEV_173: room: CHG
PR5212 PR5220 PR5223 PR5228 PR5229 PR5231 PR5238 PR5239 PR5243 PR5246 PR5251 PR5256 PR5257 PR5264 PR5505 PR5507 PR5602 PR5603 PR5607 PR5610 PR5611 PR5613 PR5614 PR5618 PR5621 PR5622 PR5810 PR5812 R34 R154 R218 R219 R223 R332 R336 R374 R378 R379 R400 R406 R418 R422 R424 R435 R438 R441 R444 R449 R450 R461 R717 R734 R2723 R9435 R9436 R9445 R9458 R9492 R9501 R9567 R9569 R9571-R9582 R9585 R9586 R9593 R9615-R9617 R9626 R9632-R9635 R9639 R9640 R9644-R9648 R9657 R9671 R9674 R9682 R9685-R9687 R9689 R9694-R9698 RC40 RC79 RC82 RC84 RC95 RC101 RC297 RC298 RC338 RC371 RC375 RC377-RC379 RC388 RC390 RC401-RC404 RC415-RC418 RC424-RC440 RC443 RC446 RC450-RC454 RC456-RC458 RC464 RC465 RC469 RC473 RC474 RC491 RC600 RC604-RC607 RC611 RC612 RC615 RC616 RC624 RD62-RD64 RD66-RD74 RI27-RI30 RI32 RI33 = DEV_118
PR5217 PR5222 PR5247 = DEV_108: room: CHG
PR5224 = DEV_330
PR5225 PR5509 PR5612 PR5623 = DEV_113: room: 1.05VS
PR5226 = DEV_242
PR5227 = DEV_348
PR5230 = DEV_241: room: CHG
PR5232 = DEV_366
PR5234 PR5302 PR5303 PR5401 PR5901 PR5905 PR5909 = DEV_22
PR5235 = DEV_240: room: CHG
PR5237 = DEV_239: room: CHG
PR5241 = DEV_238: room: CHG
PR5248 = DEV_107: room: CHG
PR5249 = DEV_237
PR5252 = DEV_106
PR5253 PR5819 = DEV_105
PR5254 = DEV_117: room: CHG
PR5258 = DEV_103
PR5261 = DEV_104
PR5301 PR5305 PR5902 PR5906 PR5910 = DEV_6: room: 1.05VS
PR5306 PR5407 PR5409 PR5501 PR5808 PR5814 PR5817 PR5824 PR5913 PR5915 = DEV_118: room: COR
PR5307 = DEV_318
PR5310 = DEV_112
PR5311 = DEV_115: room: SYS
PR5313 = DEV_378
PR5402 = DEV_317
PR5403 = DEV_240: room: 1.05VS
PR5404 = DEV_110
PR5405 = DEV_236
PR5406 = DEV_235
PR5408 = DEV_115: room: COR
PR5502 = DEV_141
PR5503 = DEV_234: room: 1.05VS
PR5504 = DEV_233
PR5506 PR5701 PR5706 PR5711 PR5719 PR6092 = DEV_118: room: 1.05VS
PR5601 PR5606 PR5608 PR5609 PR5616 PR5617 PR5619 PR5620 = DEV_115: room: 1.05VS
PR5605 PR5615 = DEV_232: room: DDR
PR5702 PR5707 PR5712 PR5718 = DEV_231: room: 1.5V&1.8V
PR5703 PR5708 PR5713 PR5717 = DEV_113: room: 1.5V&1.8V
PR5704 PR5709 = DEV_115: room: 1.5V&1.8V
PR5705 = DEV_114: room: 1.5V&1.8V
PR5710 = DEV_111: room: 1.5V&1.8V
PR5714 = DEV_230: room: 1.5V&1.8V
PR5715 = DEV_229: room: 1.5V&1.8V
PR5716 = DEV_347: room: 1.5V&1.8V
PR5720 = DEV_346: room: 1.5V&1.8V
PR5801 = DEV_301
PR5802 = DEV_345
PR5803 PR5804 = DEV_228
PR5807 R388 RC88-RC91 RC113 RC114 = DEV_170
PR5809 = DEV_150: room: COR
PR5811 = DEV_300
PR5815 = DEV_329
PR5816 = DEV_227
PR5818 PR5836 PR5847 R1 R2 R184 R321 R338 R349 R353 R367 R383 R386 R2740 R2742 R7103 R7104 R9387 R9420 RC9 RC28 RC30 RC48 RC67 RC69 RC80 RC130 RC132 RC224 RC339 RC357 RC358 RC368 RC372 RC373 RC376 RC380 RC387 RC389 RC393 RC395 RC396 RC398-RC400 RC405 RC406 RC455 RC618 RD4 RD61 RTCR1 = DEV_140
PR5821 PR5839 PR5845 = DEV_226
PR5822 = DEV_299
PR5823 = DEV_225
PR5825 PR5830 PR5851 = DEV_298
PR5826 = DEV_297
PR5827 PR5829 PR5849 = DEV_224
PR5828 = DEV_352
PR5831 = DEV_223
PR5832 = DEV_356
PR5833 PR5834 = DEV_296
PR5838 = DEV_295
PR5842 = DEV_294
PR5843 PR5844 = DEV_293
PR5846 = DEV_292
PR5850 = DEV_351
PR5853 = DEV_291
PR5903 PR5907 PR5911 = DEV_222
PR5914 PR5916 = DEV_221
PR7401 = DEV_373
PR7402 = DEV_372
PR7403 = DEV_229
PR7404 = DEV_375
PR7406 = DEV_371
PR7408 = DEV_377
PT5101 = DEV_2
PU1 = DEV_41
PU5201 = DEV_220
PU5202 U24 UC3 UC8-UC14 = DEV_40
PU5203 = DEV_16
PU5301 = DEV_85
PU5401 = DEV_49
PU5501 = DEV_219
PU5601 PU5602 = DEV_344
PU5701-PU5703 PU5904 = DEV_218
PU5801 = DEV_290
PU5901 PU5903 = DEV_86
PU5902 = DEV_217
PU7401 = DEV_370
PU7402 = DEV_376
Q1 Q216 Q3601 Q3604 Q3609 Q3610 Q4199 Q4210 Q4211 Q4213 Q4214 Q4216 = DEV_28
Q2 = DEV_29: room: CHG
Q16 Q144 = DEV_189
R32 = DEV_147
R45 R57 R9388 R9502-R9511 R9514 R9520 R9522 R9625 R9681 = DEV_8
R74 RC52 = DEV_149
R94 R99 R9414 = DEV_343
R95 R176 R178 R355-R357 R381 R385 R404 R405 R9562 R9563 R9683 = DEV_139
R107 R316 R3603 RC340 RD14 RD15 = DEV_4
R130 RC442 = DEV_153
R142 R152 R153 R169 R175 R180 R183 R427 R431 R472 R2741 R2743 R9450 R9451 R9499 R9512 R9513 R9521 R9523-R9525 R9533 R9641 R9662 R9675 R9676 RC342 RC623 = DEV_9
R148 = DEV_151
R162 R166 R325 R382 = DEV_150
R185 = DEV_109
R272 = DEV_24
R375 = DEV_146
R392 = DEV_381
R394 = DEV_213
R402 R9560 RC27 RC227 RC228 RC622 = DEV_137
R462-R469 RD3 = DEV_167
R801 = DEV_142
R802 = DEV_212
R2602 RC172 RC189 RC582 RC586 RC587 RC590 RC591 RC594 RC595 RC613 = DEV_5: room: COR
R2704 R9442 = DEV_148
R2720 = DEV_216
R2739 = DEV_23
R2744-R2746 = DEV_215
R2747 R2748 = DEV_369
R2803 R9401 R9443 RC381 RC382 = DEV_138
R2810 = DEV_107
R3701 = DEV_214
R9483 R9486 = DEV_334
R9488 = DEV_368
R9536 RC133 RC386 = DEV_211
R9584 = DEV_289
R9658-R9661 = DEV_316
RC20 RC45 RC249 RC260 RC421 RC423 RC449 = DEV_60
RC21 RC96 = DEV_144
RC36 RC37 = DEV_363
RC47 RC50 RC51 RC59 RC190 RC585 = DEV_10
RC58 RC64-RC66 RC619 = DEV_175
RC68 RC126 = DEV_143
RC83 RC128 RC134 = DEV_168
RC117 = DEV_210
RC186 RC192 RC348 RC349 = DEV_176
RC244 = DEV_209
RC248 = DEV_208
RC278 = DEV_207
RC324 = DEV_206
RC341 = DEV_173
RC347 RC350 = DEV_7
RC359 RC360 RC362-RC366 RC369 = DEV_145
RC444 RC445 = DEV_360
RC460-RC463 = DEV_312
RC471 RC472 = DEV_205: room: COR
RC593 = DEV_204
RI31 = DEV_367
RN31 RN4107 = DEV_342
RN246-RN249 RN483 RN2728 RN3601 RN4100-RN4106 RN4149-RN4152 = DEV_70
RP2 = DEV_20
RP6 RP8 = DEV_21
RP9 RP10 RP4808 = DEV_163
RP4804 RP4806 = DEV_46
RP4807 RP4810 RP4811 = DEV_87
SW5 = DEV_99
T92 T93 T2703-T2707 T6203 T6204 T6207-T6213 T6215-T6220 T6249 T6256 T6263 T6265 T6266 T6271-T6273 T6294-T6306 T6340 T6353 T6354 T7101 T7108-T7123 T7136-T7142 T7149 T7150 T7157-T7164 = DEV_3
U1 = DEV_197
U2 = DEV_19
U5 U6218 = DEV_48
U6 = DEV_198
U7 = DEV_66
U9 = DEV_172
U15 = DEV_203
U17 = DEV_202
U18 U43 U45 U46 U51 U6217 = DEV_18
U21 = DEV_201
U22 = DEV_52
U25 = DEV_200
U26 = DEV_335
U32 = DEV_17
U37 = DEV_94
U38 = DEV_199
U92 = DEV_92
U6202 = DEV_93
U6203 = DEV_59
U6204 = DEV_333
U6205 U6206 = DEV_311
U6220 = DEV_355
U6221 U6222 = DEV_307
UC1 = DEV_339
UC6 = DEV_51
US2 = DEV_57
X1 = DEV_310
Y1 = DEV_192
Y4 = DEV_69
Y8 = DEV_191
YC2 = DEV_1
YC3 = DEV_39

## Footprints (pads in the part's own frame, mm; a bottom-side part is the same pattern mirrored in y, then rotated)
1MM_OPEN_5MIL_M1M2
  custom 0.254x0.254 smd: 1(0.036,-0.472) 2(0.043,0.533)
2MM_OPEN_5MIL_M1M2
  custom 0.508x0.508 smd: 1(0,-0.699) 2(0,0.699)
2R4P0603_H28
  rect 0.508x0.838 smd: 1(-0.4,-0.825) 2(-0.4,0.825) 3(0.4,-0.825) 4(0.4,0.825)
3MM_OPEN_5MIL_M1M2
  custom 0.572x0.572 smd: 1(0,0.5) 2(0,-1.8)
4R8P0402_H20
  rect 0.498x0.61 smd: 1(-0.852,-0.495) 2(-0.852,0.495) 7(0.852,-0.495) 8(0.852,0.495)
  rect 0.295x0.61 smd: 3(-0.25,-0.495) 4(-0.25,0.495) 5(0.25,-0.495) 6(0.25,0.495)
4R8P_H24
  rect 0.635x0.94 smd: 1(-1.289,-0.818) 2(-1.289,0.818) 7(1.289,-0.818) 8(1.289,0.818)
  rect 0.457x0.94 smd: 3(-0.4,-0.818) 4(-0.4,0.818) 5(0.4,-0.818) 6(0.4,0.818)
8R10P
  rect 0.508x0.94 smd: 1(-1.369,-0.868) 5(1.369,-0.868) 6(1.369,0.868) 10(-1.369,0.868)
  rect 0.33x0.94 smd: 2(-0.64,-0.868) 3(0,-0.868) 4(0.64,-0.868) 7(0.64,0.868) 8(0,0.868) 9(-0.64,0.868)
BATT_9P_79_2HD_SUYIN_LF5
  rect 1.702x1.702 hole 1.118: 1(-8,0)
  round 1.702 hole 1.118: 2(-6,0) 3(-4,0) 4(-2,0) 5(0,0) 6(2,0) 7(4,0) 8(6,0) 9(8,0)
  oval 2.184x4.039 hole 0.991: 10(-11.125,0) 11(11.125,0)
BGA_168P_26_335X394
  round 0.305 smd: A1(-3.575,-4.225) A2(-3.575,-3.575) A3(-3.575,-2.925) A4(-3.575,-2.275) A5(-3.575,-1.625) A6(-3.575,-0.975) A7(-3.575,-0.325) A8(-3.575,0.325) A9(-3.575,0.975) A10(-3.575,1.625) A11(-3.575,2.275) A12(-3.575,2.925) A13(-3.575,3.575) A14(-3.575,4.225) B1(-2.925,-4.225) B2(-2.925,-3.575) B3(-2.925,-2.925) B4(-2.925,-2.275) B5(-2.925,-1.625) B6(-2.925,-0.975) B7(-2.925,-0.325) B8(-2.925,0.325) B9(-2.925,0.975) B10(-2.925,1.625) B11(-2.925,2.275) B12(-2.925,2.925) B13(-2.925,3.575) B14(-2.925,4.225) C1(-2.275,-4.225) C2(-2.275,-3.575) C3(-2.275,-2.925) C4(-2.275,-2.275) C5(-2.275,-1.625) C6(-2.275,-0.975) C7(-2.275,-0.325) C8(-2.275,0.325) C9(-2.275,0.975) C10(-2.275,1.625) C11(-2.275,2.275) C12(-2.275,2.925) C13(-2.275,3.575) C14(-2.275,4.225) D1(-1.625,-4.225) D2(-1.625,-3.575) D3(-1.625,-2.925) D4(-1.625,-2.275) D5(-1.625,-1.625) D6(-1.625,-0.975) D7(-1.625,-0.325) D8(-1.625,0.325) D9(-1.625,0.975) D10(-1.625,1.625) D11(-1.625,2.275) D12(-1.625,2.925) D13(-1.625,3.575) D14(-1.625,4.225) E1(-0.975,-4.225) E2(-0.975,-3.575) E3(-0.975,-2.925) E4(-0.975,-2.275) E5(-0.975,-1.625) E6(-0.975,-0.975) E7(-0.975,-0.325) E8(-0.975,0.325) E9(-0.975,0.975) E10(-0.975,1.625) E11(-0.975,2.275) E12(-0.975,2.925) E13(-0.975,3.575) E14(-0.975,4.225) F1(-0.325,-4.225) F2(-0.325,-3.575) F3(-0.325,-2.925) F4(-0.325,-2.275) F5(-0.325,-1.625) F6(-0.325,-0.975) F7(-0.325,-0.325) F8(-0.325,0.325) F9(-0.325,0.975) F10(-0.325,1.625) F11(-0.325,2.275) F12(-0.325,2.925) F13(-0.325,3.575) F14(-0.325,4.225) G1(0.325,-4.225) G2(0.325,-3.575) G3(0.325,-2.925) G4(0.325,-2.275) G5(0.325,-1.625) G6(0.325,-0.975) G7(0.325,-0.325) G8(0.325,0.325) G9(0.325,0.975) G10(0.325,1.625) G11(0.325,2.275) G12(0.325,2.925) G13(0.325,3.575) G14(0.325,4.225) H1(0.975,-4.225) H2(0.975,-3.575) H3(0.975,-2.925) H4(0.975,-2.275) H5(0.975,-1.625) H6(0.975,-0.975) H7(0.975,-0.325) H8(0.975,0.325) H9(0.975,0.975) H10(0.975,1.625) H11(0.975,2.275) H12(0.975,2.925) H13(0.975,3.575) H14(0.975,4.225) J1(1.625,-4.225) J2(1.625,-3.575) J3(1.625,-2.925) J4(1.625,-2.275) J5(1.625,-1.625) J6(1.625,-0.975) J7(1.625,-0.325) J8(1.625,0.325) J9(1.625,0.975) J10(1.625,1.625) J11(1.625,2.275) J12(1.625,2.925) J13(1.625,3.575) J14(1.625,4.225) K1(2.275,-4.225) K2(2.275,-3.575) K3(2.275,-2.925) K4(2.275,-2.275) K5(2.275,-1.625) K6(2.275,-0.975) K7(2.275,-0.325) K8(2.275,0.325) K9(2.275,0.975) K10(2.275,1.625) K11(2.275,2.275) K12(2.275,2.925) K13(2.275,3.575) K14(2.275,4.225) L1(2.925,-4.225) L2(2.925,-3.575) L3(2.925,-2.925) L4(2.925,-2.275) L5(2.925,-1.625) L6(2.925,-0.975) L7(2.925,-0.325) L8(2.925,0.325) L9(2.925,0.975) L10(2.925,1.625) L11(2.925,2.275) L12(2.925,2.925) L13(2.925,3.575) L14(2.925,4.225) M1(3.575,-4.225) M2(3.575,-3.575) M3(3.575,-2.925) M4(3.575,-2.275) M5(3.575,-1.625) M6(3.575,-0.975) M7(3.575,-0.325) M8(3.575,0.325) M9(3.575,0.975) M10(3.575,1.625) M11(3.575,2.275) M12(3.575,2.925) M13(3.575,3.575) M14(3.575,4.225)
BGA_1356P_1654X945_INTEL
  round 0.356 smd: A3(19.349,-11.314) A70(-19.852,-11.314) B2(19.832,-10.832) B71(-20.314,-10.852) BA1(20.314,10.852) BA71(-20.314,10.852) BB2(19.852,11.314) BB70(-19.852,11.314) C1(20.314,-10.349)
  round 0.33 smd: A4(18.699,-11.314) A69(-19.202,-11.314) AY1(20.314,10.202) AY71(-20.314,10.202) B3(19.197,-10.679) B70(-19.685,-10.685) BA2(19.685,10.685) BA70(-19.685,10.685) BB3(19.202,11.314) BB69(-19.202,11.314) C2(19.679,-10.197) C71(-20.314,-10.202) D1(20.314,-9.699)
  round 0.305 smd: A5(18.048,-11.314) A68(-18.552,-11.314) AA2(19.339,-0.511) AA4(18.363,-0.511) AA63(-15.112,-0.596) AA64(-15.763,-0.596) AA65(-16.413,-0.596) AA66(-17.063,-0.596) AA67(-17.713,-0.596) AA68(-18.364,-0.596) AA69(-19.014,-0.596) AA70(-19.664,-0.596) AA71(-20.314,-0.596) AB4(18.363,0.152) AB6(17.585,-0.133) AB7(16.935,-0.133) AB8(16.285,-0.133) AB9(15.635,-0.133) AB10(14.984,-0.133) AB11(14.334,-0.133) AB12(13.684,-0.133) AB13(13.034,-0.133) AB15(12.188,-0.009) AB16(11.538,-0.009) AB17(10.888,-0.009) AB18(10.237,-0.009) AB19(9.587,-0.009) AB20(8.937,-0.009) AB21(8.287,-0.009) AB62(-14.644,-0.138) AC3(18.689,0.815) AC63(-15.112,0.319) AC64(-15.763,0.319) AC65(-16.413,0.319) AC66(-17.063,0.319) AC67(-17.713,0.319) AC68(-18.364,0.319) AC69(-19.014,0.319) AC70(-19.664,0.319) AC71(-20.314,0.319) AD4(18.363,1.478) AD6(17.585,0.934) AD7(16.935,0.934) AD8(16.285,0.934) AD9(15.635,0.934) AD10(14.984,0.934) AD11(14.334,0.934) AD12(13.684,0.934) AD13(13.034,0.934) AD15(12.188,0.829) AD16(11.538,0.829) AD17(10.888,0.829) AD18(10.237,0.829) AD19(9.587,0.829) AD20(8.937,0.829) AD21(8.287,0.829) AD62(-14.644,0.776) AE62(-14.644,1.69) AE63(-15.112,1.233) AE64(-15.763,1.233) AE65(-16.413,1.233) AE66(-17.063,1.233) AE67(-17.713,1.233) AE68(-18.364,1.233) AE69(-19.014,1.233) AF2(19.339,2.141) AF4(18.363,2.141) AF6(17.585,2.001) AF7(16.935,2.001) AF8(16.285,2.001) AF9(15.635,2.001) AF10(14.984,2.001) AF11(14.334,2.001) AF12(13.684,2.001) AF13(13.034,2.001) AF15(12.188,1.668) AF16(11.538,1.668) AF17(10.888,1.668) AF18(10.237,1.668) AF19(9.587,1.668) AF20(8.937,1.668) AF21(8.287,1.668) AF63(-15.112,2.148) AF64(-15.763,2.148) AF65(-16.413,2.148) AF66(-17.063,2.148) AF67(-17.713,2.148) AF68(-18.364,1.939) AF69(-19.014,1.939) AG4(18.363,2.804) AG15(12.188,2.506) AG16(11.538,2.506) AG17(10.888,2.506) AG18(10.237,2.506) AG19(9.587,2.506) AG20(8.937,2.506) AG21(8.287,2.506) AG62(-14.644,2.605) AG69(-18.689,2.602) AH3(18.689,3.467) AH6(17.585,3.067) AH7(16.935,3.067) AH8(16.285,3.067) AH9(15.635,3.067) AH10(14.984,3.067) AH11(14.334,3.067) AH12(13.684,3.067) AH13(13.034,3.067) AH63(-15.112,3.062) AH64(-15.763,3.062) AH65(-16.413,3.062) AH66(-17.063,3.062) AH67(-17.713,3.062) AJ4(18.363,4.13) AJ15(12.188,3.344) AJ16(11.538,3.344) AJ17(10.888,3.344) AJ18(10.237,3.344) AJ19(9.587,3.344) AJ20(8.937,3.344) AJ21(8.287,3.344) AJ62(-14.644,3.519) AK6(17.585,4.007) AK7(16.935,4.007) AK8(16.285,4.007) AK9(15.635,4.007) AK10(14.984,4.007) AK11(14.334,4.007) AK12(13.684,4.007) AK13(13.034,4.007) AK15(12.188,4.182) AK16(11.538,4.182) AK17(10.888,4.182) AK18(10.237,4.182) AK19(9.587,4.182) AK20(8.937,4.182) AK21(8.287,4.182) AK22(7.596,4.009) AK23(6.681,4.009) AK25(5.767,4.009) AK27(4.852,4.009) AK28(3.938,4.009) AK30(3.024,4.009) AK32(2.109,4.009) AK33(1.195,4.009) AK35(0.28,4.009) AK37(-0.634,4.009) AK38(-1.548,4.009) AK40(-2.463,4.009) AK42(-3.377,4.009) AK43(-4.292,4.009) AK45(-5.206,4.009) AK46(-6.12,4.009) AK48(-7.035,4.009) AK50(-7.949,4.009) AK52(-8.864,4.009) AK53(-9.778,4.009) AK55(-10.692,4.009) AK56(-11.607,4.009) AK58(-12.521,4.009) AK60(-13.436,4.009) AK62(-14.46,4.144) AK63(-15.112,3.976) AK64(-15.763,3.976) AK65(-16.413,3.976) AK66(-17.063,3.976) AK67(-17.713,3.976) AK68(-18.364,3.829) AK69(-19.339,3.829) AL2(19.339,4.793) AL4(18.363,4.793) AL23(7.138,4.474) AL25(6.224,4.474) AL27(5.31,4.474) AL28(4.395,4.474) AL30(3.481,4.474) AL32(2.566,4.474) AL33(1.652,4.474) AL35(0.738,4.474) AL37(-0.177,4.474) AL38(-1.091,4.474) AL40(-2.006,4.474) AL42(-2.92,4.474) AL43(-3.834,4.474) AL45(-4.749,4.474) AL46(-5.663,4.474) AL48(-6.578,4.474) AL50(-7.492,4.474) AL52(-8.406,4.474) AL53(-9.321,4.474) AL55(-10.235,4.474) AL56(-11.15,4.474) AL58(-12.064,4.474) AL60(-12.978,4.474) AL61(-13.893,4.474) AL63(-15.112,4.845) AL64(-15.763,4.845) AL65(-16.413,4.845) AL66(-17.063,4.845) AM4(18.363,5.456) AM5(17.654,4.946) AM7(16.74,4.946) AM8(15.825,4.946) AM10(14.911,4.946) AM11(13.996,4.946) AM13(13.082,4.946) AM15(12.168,4.946) AM16(11.253,4.946) AM18(10.339,4.946) AM20(9.424,4.946) AM21(8.51,4.946) AM22(7.596,4.946) AM23(6.681,4.946) AM25(5.767,4.946) AM27(4.852,4.946) AM28(3.938,4.946) AM30(3.024,4.946) AM32(2.109,4.946) AM33(1.195,4.946) AM35(0.28,4.946) AM37(-0.634,4.946) AM38(-1.548,4.946) AM40(-2.463,4.946) AM42(-3.377,4.946) AM43(-4.292,4.946) AM45(-5.206,4.946) AM46(-6.12,4.946) AM48(-7.035,4.946) AM50(-7.949,4.946) AM52(-8.864,4.946) AM53(-9.778,4.946) AM55(-10.692,4.946) AM56(-11.607,4.946) AM58(-12.521,4.946) AM60(-13.436,4.946) AM61(-14.35,4.946) AM68(-18.039,5.056) AM69(-18.689,5.056) AN3(18.689,6.119) AN5(17.654,5.597) AN7(16.74,5.597) AN8(15.825,5.597) AN10(14.911,5.597) AN11(13.996,5.597) AN13(13.082,5.597) AN15(12.168,5.597) AN16(11.253,5.597) AN18(10.339,5.597) AN20(9.424,5.597) AN21(8.51,5.597) AN22(7.596,5.597) AN23(6.681,5.597) AN25(5.767,5.597) AN27(4.852,5.597) AN28(3.938,5.597) AN30(3.024,5.597) AN32(2.109,5.597) AN33(1.195,5.597) AN35(0.28,5.597) AN37(-0.634,5.597) AN38(-1.548,5.597) AN40(-2.463,5.597) AN42(-3.377,5.597) AN43(-4.292,5.597) AN45(-5.206,5.597) AN46(-6.12,5.597) AN48(-7.035,5.597) AN50(-7.949,5.597) AN52(-8.864,5.597) AN53(-9.778,5.597) AN55(-10.692,5.597) AN56(-11.607,5.597) AN58(-12.521,5.597) AN60(-13.436,5.597) AN61(-14.35,5.597) AN63(-15.264,5.597) AN65(-16.179,5.597) AN66(-17.093,5.597) AN68(-18.364,5.719) AN69(-19.014,5.719) AP4(18.363,6.782) AP5(17.654,6.247) AP7(16.74,6.247) AP8(15.825,6.247) AP10(14.911,6.247) AP11(13.996,6.247) AP13(13.082,6.247) AP15(12.168,6.247) AP16(11.253,6.247) AP18(10.339,6.247) AP20(9.424,6.247) AP21(8.51,6.247) AP22(7.596,6.247) AP23(6.681,6.247) AP25(5.767,6.247) AP27(4.852,6.247) AP28(3.938,6.247) AP30(3.024,6.247) AP32(2.109,6.247) AP33(1.195,6.247) AP35(0.28,6.247) AP37(-0.634,6.247) AP38(-1.548,6.247) AP40(-2.463,6.247) AP42(-3.377,6.247) AP43(-4.292,6.247) AP45(-5.206,6.247) AP46(-6.12,6.247) AP48(-7.035,6.247) AP50(-7.949,6.247) AP52(-8.864,6.247) AP53(-9.778,6.247) AP55(-10.692,6.247) AP56(-11.607,6.247) AP58(-12.521,6.247) AP60(-13.436,6.247) AP61(-14.35,6.247) AP63(-15.264,6.247) AP65(-16.179,6.247) AP66(-17.093,6.247) AP68(-18.039,6.332) AP70(-19.258,6.332) AR5(17.654,6.897) AR7(16.74,6.897) AR8(15.825,6.897) AR10(14.911,6.897) AR11(13.996,6.897) AR13(13.082,6.897) AR15(12.168,6.897) AR16(11.253,6.897) AR18(10.339,6.897) AR20(9.424,6.897) AR21(8.51,6.897) AR22(7.596,6.897) AR23(6.681,6.897) AR25(5.767,6.897) AR27(4.852,6.897) AR28(3.938,6.897) AR30(3.024,6.897) AR32(2.109,6.897) AR33(1.195,6.897) AR35(0.28,6.897) AR37(-0.634,6.897) AR38(-1.548,6.897) AR40(-2.463,6.897) AR42(-3.377,6.897) AR43(-4.292,6.897) AR45(-5.206,6.897) AR46(-6.12,6.897) AR48(-7.035,6.897) AR50(-7.949,6.897) AR52(-8.864,6.897) AR53(-9.778,6.897) AR55(-10.692,6.897) AR56(-11.607,6.897) AR58(-12.521,6.897) AR60(-13.436,6.897) AR61(-14.35,6.897) AR63(-15.264,6.897) AR65(-16.179,6.897) AR66(-17.093,6.897) AR68(-18.364,6.945) AR69(-19.014,6.945) AT2(19.339,7.445) AT4(18.363,7.445) AT5(17.654,7.547) AT7(16.74,7.547) AT8(15.825,7.547) AT10(14.911,7.547) AT11(13.996,7.547) AT13(13.082,7.547) AT15(12.168,7.547) AT16(11.253,7.547) AT18(10.339,7.547) AT20(9.424,7.547) AT21(8.51,7.547) AT22(7.596,7.547) AT23(6.681,7.547) AT25(5.767,7.547) AT27(4.852,7.547) AT28(3.938,7.547) AT30(3.024,7.547) AT32(2.109,7.547) AT33(1.195,7.547) AT35(0.28,7.547) AT37(-0.634,7.547) AT38(-1.548,7.547) AT40(-2.463,7.547) AT42(-3.377,7.547) AT43(-4.292,7.547) AT45(-5.206,7.547) AT46(-6.12,7.547) AT48(-7.035,7.547) AT50(-7.949,7.547) AT52(-8.864,7.547) AT53(-9.778,7.547) AT55(-10.692,7.547) AT56(-11.607,7.547) AT58(-12.521,7.547) AT60(-13.436,7.547) AT61(-14.35,7.547) AT63(-15.264,7.547) AT65(-16.179,7.547) AT66(-17.093,7.547) AT68(-18.039,7.509) AT69(-18.689,7.509) AU4(18.363,8.108) AU5(17.654,8.198) AU7(16.74,8.198) AU8(15.825,8.198) AU10(14.911,8.198) AU11(13.996,8.198) AU13(13.082,8.198) AU15(12.168,8.198) AU16(11.253,8.198) AU18(10.339,8.198) AU20(9.424,8.198) AU21(8.51,8.198) AU22(7.596,8.198) AU23(6.681,8.198) AU25(5.767,8.198) AU27(4.852,8.198) AU28(3.938,8.198) AU30(3.024,8.198) AU32(2.109,8.198) AU33(1.195,8.198) AU35(0.28,8.198) AU37(-0.634,8.198) AU38(-1.548,8.198) AU40(-2.463,8.198) AU42(-3.377,8.198) AU43(-4.292,8.198) AU45(-5.206,8.198) AU46(-6.12,8.198) AU48(-7.035,8.198) AU50(-7.949,8.198) AU52(-8.864,8.198) AU53(-9.778,8.198) AU55(-10.692,8.198) AU56(-11.607,8.198) AU58(-12.521,8.198) AU60(-13.436,8.198) AU61(-14.35,8.198) AU63(-15.264,8.198) AU65(-16.179,8.198) AU66(-17.093,8.198) AV3(18.689,8.799) AV68(-18.029,8.711) AV69(-19.014,8.901) AV70(-19.664,8.901) AW1(20.314,9.551) AW5(17.781,8.911) AW6(17.13,9.038) AW7(16.564,9.363) AW8(15.986,9.038) AW9(15.416,9.363) AW10(14.753,9.038) AW11(14.143,9.363) AW12(13.565,9.038) AW13(12.995,9.363) AW14(12.332,9.038) AW15(11.723,9.363) AW16(11.145,9.038) AW17(10.575,9.363) AW18(9.912,9.038) AW20(9.302,9.363) AW21(8.724,9.038) AW22(8.154,9.363) AW23(7.466,9.038) AW25(6.828,9.363) AW26(6.264,9.038) AW27(5.601,9.363) AW28(4.988,9.038) AW29(4.374,9.363) AW30(3.711,9.038) AW31(3.148,9.363) AW32(2.485,9.038) AW33(1.847,9.363) AW34(1.283,9.038) AW35(0.62,9.363) AW36(0.007,9.038) AW37(-0.607,9.363) AW38(-1.269,9.038) AW39(-1.833,9.363) AW41(-2.471,9.038) AW42(-3.108,9.363) AW43(-3.672,9.038) AW44(-4.335,9.363) AW45(-4.949,9.038) AW46(-5.562,9.363) AW47(-6.163,9.038) AW48(-6.727,9.363) AW49(-7.355,9.038) AW50(-7.984,9.363) AW51(-8.548,9.038) AW52(-9.149,9.363) AW53(-9.762,9.038) AW54(-10.375,9.363) AW55(-11.038,9.038) AW56(-11.602,9.363) AW57(-12.24,9.038) AW59(-12.877,9.363) AW60(-13.441,9.038) AW61(-14.104,9.363) AW62(-14.718,9.038) AW63(-15.331,9.363) AW64(-15.994,9.038) AW65(-16.558,9.363) AW66(-17.093,8.9) AW67(-18.018,9.371) AW68(-18.622,9.622) AW69(-19.267,9.536) AW70(-19.685,10.035) AW71(-20.314,9.551) AY2(19.685,10.034) AY3(19.028,10.028) AY4(18.274,10.043) AY5(17.665,9.689) AY8(15.986,9.689) AY12(13.565,9.689) AY16(11.145,9.689) AY21(8.724,9.689) AY26(6.264,9.689) AY27(5.601,10.014) AY29(4.374,10.014) AY30(3.711,9.689) AY34(1.283,9.689) AY35(0.62,10.014) AY37(-0.607,10.014) AY38(-1.269,9.689) AY43(-3.672,9.689) AY44(-4.335,10.014) AY46(-5.562,10.014) AY47(-6.163,9.689) AY51(-8.548,9.689) AY52(-9.149,10.014) AY54(-10.375,10.014) AY55(-11.038,9.689) AY60(-13.441,9.689) AY61(-14.104,10.014) AY63(-15.331,10.014) AY64(-15.994,9.689) AY66(-17.221,9.689) AY68(-18.535,10.267) B5(18.048,-10.664) B6(17.467,-10.339) B10(14.989,-10.339) B14(12.511,-10.339) B18(10.033,-10.339) B22(7.555,-10.339) B26(5.077,-10.339) B30(2.599,-10.339) B34(0.121,-10.339) B39(-2.357,-10.339) B44(-4.835,-10.339) B48(-7.313,-10.339) B53(-9.791,-10.339) B58(-12.269,-10.339) B62(-14.747,-10.339) B66(-17.226,-10.339) B69(-19.035,-10.685) BA3(19.035,10.685) BA5(17.715,10.626) BA8(15.986,10.339) BA12(13.565,10.339) BA16(11.145,10.339) BA21(8.724,10.339) BA23(7.466,10.258) BA28(4.988,10.258) BA32(2.485,10.258) BA36(0.007,10.258) BA41(-2.471,10.258) BA45(-4.949,10.258) BA49(-7.355,10.339) BA53(-9.762,10.258) BA57(-12.24,10.258) BA62(-14.718,10.258) BA68(-19.035,10.685) BB4(18.551,11.314) BB68(-18.552,11.314) C4(18.615,-10.336) C5(18.048,-10.014) C7(16.791,-10.014) C8(16.228,-10.339) C9(15.664,-10.014) C11(14.313,-10.014) C12(13.75,-10.339) C13(13.186,-10.014) C15(11.835,-10.014) C16(11.272,-10.339) C17(10.708,-10.014) C19(9.357,-10.014) C20(8.794,-10.339) C21(8.23,-10.014) C23(6.879,-10.014) C24(6.316,-10.339) C25(5.752,-10.014) C27(4.401,-10.014) C28(3.838,-10.339) C29(3.274,-10.014) C31(1.923,-10.014) C32(1.36,-10.339) C33(0.796,-10.014) C36(-0.555,-10.014) C37(-1.118,-10.339) C38(-1.682,-10.014) C40(-3.033,-10.014) C41(-3.596,-10.339) C42(-4.16,-10.014) C45(-5.511,-10.014) C46(-6.074,-10.339) C47(-6.638,-10.014) C50(-7.989,-10.014) C51(-8.552,-10.339) C52(-9.116,-10.014) C54(-10.467,-10.014) C55(-11.03,-10.339) C56(-11.594,-10.014) C59(-12.945,-10.014) C60(-13.508,-10.339) C61(-14.072,-10.014) C63(-15.423,-10.014) C64(-15.987,-10.339) C65(-16.55,-10.014) C67(-18.485,-10.299) C68(-18.622,-9.622) C70(-19.685,-10.034) D3(19.339,-9.608) D4(18.691,-9.669) D5(18.09,-9.363) D6(17.441,-9.323) D7(16.791,-9.363) D8(16.228,-9.689) D9(15.664,-9.363) D10(14.989,-9.323) D11(14.313,-9.363) D12(13.75,-9.689) D13(13.186,-9.363) D14(12.511,-9.323) D15(11.835,-9.363) D16(11.272,-9.689) D17(10.708,-9.363) D18(10.033,-9.323) D19(9.357,-9.363) D20(8.794,-9.689) D21(8.23,-9.363) D22(7.555,-9.323) D23(6.879,-9.363) D24(6.316,-9.689) D25(5.752,-9.363) D26(5.077,-9.323) D27(4.401,-9.363) D28(3.838,-9.689) D29(3.274,-9.363) D30(2.599,-9.323) D31(1.923,-9.363) D32(1.36,-9.689) D33(0.796,-9.363) D34(0.121,-9.323) D36(-0.555,-9.363) D37(-1.118,-9.689) D38(-1.682,-9.363) D39(-2.357,-9.323) D40(-3.033,-9.363) D41(-3.596,-9.689) D42(-4.16,-9.363) D44(-4.835,-9.323) D45(-5.511,-9.363) D46(-6.074,-9.689) D47(-6.638,-9.363) D48(-7.313,-9.323) D50(-7.989,-9.363) D51(-8.552,-9.689) D52(-9.116,-9.363) D53(-9.791,-9.323) D54(-10.467,-9.363) D55(-11.03,-9.689) D56(-11.594,-9.363) D58(-12.269,-9.323) D59(-12.945,-9.363) D60(-13.508,-9.689) D61(-14.072,-9.363) D62(-14.747,-9.323) D63(-15.423,-9.363) D64(-15.987,-9.689) D65(-16.55,-9.363) D66(-17.226,-9.323) D67(-17.899,-10.014) D68(-19.267,-9.535) D69(-18.562,-8.971) D71(-20.314,-9.551) E1(20.314,-9.04) E2(19.664,-9.04) E3(19.014,-9.04) E5(17.654,-8.591) E6(16.74,-8.591) E8(15.825,-8.591) E10(14.911,-8.591) E11(13.996,-8.591) E13(13.082,-8.591) E15(12.168,-8.591) E16(11.253,-8.591) E18(10.339,-8.591) E20(9.424,-8.591) E21(8.51,-8.591) E22(7.596,-8.591) E23(6.681,-8.591) E25(5.767,-8.591) E27(4.852,-8.591) E28(3.938,-8.591) E30(3.024,-8.591) E32(2.109,-8.591) E33(1.195,-8.591) E35(0.28,-8.591) E37(-0.634,-8.591) E38(-1.548,-8.591) E40(-2.463,-8.591) E42(-3.377,-8.591) E43(-4.292,-8.591) E45(-5.206,-8.591) E46(-6.12,-8.591) E48(-7.035,-8.591) E50(-7.949,-8.591) E52(-8.864,-8.591) E53(-9.778,-8.591) E55(-10.692,-8.591) E56(-11.607,-8.591) E58(-12.521,-8.591) E60(-13.436,-8.591) E61(-14.35,-8.591) E63(-15.315,-8.655) E65(-16.331,-8.655) E66(-17.347,-8.655) E68(-17.899,-9.363) F2(19.339,-8.466) F4(18.363,-8.466) F5(17.654,-7.941) F6(16.74,-7.941) F8(15.825,-7.941) F10(14.911,-7.941) F11(13.996,-7.941) F13(13.082,-7.941) F15(12.168,-7.941) F16(11.253,-7.941) F18(10.339,-7.941) F20(9.424,-7.941) F21(8.51,-7.941) F22(7.596,-7.941) F23(6.681,-7.941) F25(5.767,-7.941) F27(4.852,-7.941) F28(3.938,-7.941) F30(3.024,-7.941) F32(2.109,-7.941) F33(1.195,-7.941) F35(0.28,-7.941) F37(-0.634,-7.941) F38(-1.548,-7.941) F40(-2.463,-7.941) F42(-3.377,-7.941) F43(-4.292,-7.941) F45(-5.206,-7.941) F46(-6.12,-7.941) F48(-7.035,-7.941) F50(-7.949,-7.941) F52(-8.864,-7.941) F53(-9.778,-7.941) F55(-10.692,-7.941) F56(-11.607,-7.941) F58(-12.521,-7.941) F60(-13.436,-7.941) F61(-14.35,-7.941) F63(-15.315,-8.005) F65(-16.331,-8.005) F66(-17.347,-8.005) F68(-18.562,-8.32) G4(18.363,-7.803) G5(17.654,-7.291) G6(16.74,-7.291) G8(15.825,-7.291) G10(14.911,-7.291) G11(13.996,-7.291) G13(13.082,-7.291) G15(12.168,-7.291) G16(11.253,-7.291) G18(10.339,-7.291) G20(9.424,-7.291) G21(8.51,-7.291) G22(7.596,-7.291) G23(6.681,-7.291) G25(5.767,-7.291) G27(4.852,-7.291) G28(3.938,-7.291) G30(3.024,-7.291) G32(2.109,-7.291) G33(1.195,-7.291) G35(0.28,-7.291) G37(-0.634,-7.291) G38(-1.548,-7.291) G40(-2.463,-7.291) G42(-3.377,-7.291) G43(-4.292,-7.291) G45(-5.206,-7.291) G46(-6.12,-7.291) G48(-7.035,-7.291) G50(-7.949,-7.291) G52(-8.864,-7.291) G53(-9.778,-7.291) G55(-10.692,-7.291) G56(-11.607,-7.291) G58(-12.521,-7.291) G60(-13.436,-7.291) G61(-14.35,-7.291) G63(-15.315,-7.354) G65(-16.331,-7.354) G66(-17.347,-7.354) G68(-18.364,-7.66) G69(-19.014,-7.66) H3(18.689,-7.14) H5(17.654,-6.641) H6(16.74,-6.641) H8(15.825,-6.641) H10(14.911,-6.641) H11(13.996,-6.641) H13(13.082,-6.641) H15(12.168,-6.641) H16(11.253,-6.641) H18(10.339,-6.641) H20(9.424,-6.641) H21(8.51,-6.641) H63(-15.315,-6.704) H65(-16.331,-6.704) H66(-17.347,-6.704) H69(-18.689,-7.096) J4(18.363,-6.477) J5(17.654,-5.99) J6(16.74,-5.99) J8(15.825,-5.99) J10(14.911,-5.99) J11(13.996,-5.99) J13(13.082,-5.99) J22(7.138,-6.827) J23(6.224,-6.827) J25(5.31,-6.827) J27(4.395,-6.827) J28(3.481,-6.827) J30(2.566,-6.827) J32(1.652,-6.827) J33(0.738,-6.827) J35(-0.177,-6.827) J37(-1.091,-6.827) J38(-2.006,-6.827) J40(-2.92,-6.827) J42(-3.834,-6.827) J43(-4.749,-6.827) J45(-5.663,-6.827) J46(-6.578,-6.827) J48(-7.492,-6.827) J50(-8.406,-6.827) J52(-9.321,-6.827) J53(-10.235,-6.827) J55(-11.15,-6.827) J56(-12.064,-6.827) J58(-12.978,-6.827) J60(-13.893,-6.827) J68(-18.362,-6.52) K15(12.188,-5.876) K16(11.538,-5.876) K17(10.888,-5.876) K18(10.237,-5.876) K19(9.587,-5.876) K20(8.937,-5.876) K21(8.287,-5.876) K22(7.596,-6.362) K23(6.681,-6.362) K25(5.767,-6.362) K27(4.852,-6.362) K28(3.938,-6.362) K30(3.024,-6.362) K32(2.109,-6.362) K33(1.195,-6.362) K35(0.28,-6.362) K37(-0.634,-6.362) K38(-1.548,-6.362) K40(-2.463,-6.362) K42(-3.377,-6.362) K43(-4.292,-6.362) K45(-5.206,-6.362) K46(-6.12,-6.362) K48(-7.035,-6.362) K50(-7.949,-6.362) K52(-8.864,-6.362) K53(-9.778,-6.362) K55(-10.692,-6.362) K56(-11.607,-6.362) K58(-12.521,-6.362) K60(-13.436,-6.362) K61(-14.35,-6.362) K63(-15.133,-6.054) K64(-15.783,-6.054) K65(-16.433,-6.054) K66(-17.084,-6.054) K67(-17.734,-6.054) K68(-18.352,-5.846) K70(-19.339,-5.744) L2(19.339,-5.814) L4(18.363,-5.814) L6(17.585,-5.34) L7(16.935,-5.34) L8(16.285,-5.34) L9(15.635,-5.34) L10(14.984,-5.34) L11(14.334,-5.34) L12(13.684,-5.34) L13(13.034,-5.34) L15(12.188,-5.038) L16(11.538,-5.038) L17(10.888,-5.038) L18(10.237,-5.038) L19(9.587,-5.038) L20(8.937,-5.038) L21(8.287,-5.038) L62(-14.644,-5.625) L63(-15.112,-5.168) L64(-15.763,-5.168) L65(-16.413,-5.168) L66(-17.063,-5.168) L67(-17.713,-5.168) L68(-18.364,-5.168) L69(-19.014,-5.168) L70(-19.664,-5.168) L71(-20.314,-5.168) M4(18.363,-5.151) M62(-14.644,-4.71) N3(18.689,-4.488) N6(17.585,-4.4) N7(16.935,-4.4) N8(16.285,-4.4) N9(15.635,-4.4) N10(14.984,-4.4) N11(14.334,-4.4) N12(13.684,-4.4) N13(13.034,-4.4) N15(12.188,-4.2) N16(11.538,-4.2) N17(10.888,-4.2) N18(10.237,-4.2) N19(9.587,-4.2) N20(8.937,-4.2) N21(8.287,-4.2) N63(-15.112,-4.253) N64(-15.763,-4.253) N65(-16.413,-4.253) N66(-17.063,-4.253) N67(-17.713,-4.253) N68(-18.364,-4.253) N69(-19.014,-4.253) N70(-19.664,-4.253) N71(-20.314,-4.253) P4(18.363,-3.825) P15(12.188,-3.362) P16(11.538,-3.362) P17(10.888,-3.362) P18(10.237,-3.362) P19(9.587,-3.362) P20(8.937,-3.362) P21(8.287,-3.362) P62(-14.644,-3.796) R6(17.585,-3.333) R7(16.935,-3.333) R8(16.285,-3.333) R9(15.635,-3.333) R10(14.984,-3.333) R11(14.334,-3.333) R12(13.684,-3.333) R13(13.034,-3.333) R63(-15.112,-3.339) R64(-15.763,-3.339) R65(-16.413,-3.339) R66(-17.063,-3.339) R67(-17.713,-3.339) R68(-18.364,-3.339) R69(-19.014,-3.339) R70(-19.664,-3.339) R71(-20.314,-3.339) T2(19.339,-3.162) T4(18.363,-3.162) T15(12.188,-2.523) T16(11.538,-2.523) T17(10.888,-2.523) T18(10.237,-2.523) T19(9.587,-2.523) T20(8.937,-2.523) T21(8.287,-2.523) T62(-14.644,-2.882) U4(18.363,-2.499) U6(17.585,-2.267) U7(16.935,-2.267) U8(16.285,-2.267) U9(15.635,-2.267) U10(14.984,-2.267) U11(14.334,-2.267) U12(13.684,-2.267) U13(13.034,-2.267) U63(-15.112,-2.424) U64(-15.763,-2.424) U65(-16.413,-2.424) U66(-17.063,-2.424) U67(-17.713,-2.424) U68(-18.364,-2.424) U69(-19.014,-2.424) U70(-19.664,-2.424) U71(-20.314,-2.424) V3(18.689,-1.836) V15(12.188,-1.685) V16(11.538,-1.685) V17(10.888,-1.685) V18(10.237,-1.685) V19(9.587,-1.685) V20(8.937,-1.685) V21(8.287,-1.685) V62(-14.644,-1.967) W4(18.363,-1.173) W6(17.585,-1.2) W7(16.935,-1.2) W8(16.285,-1.2) W9(15.635,-1.2) W10(14.984,-1.2) W11(14.334,-1.2) W12(13.684,-1.2) W13(13.034,-1.2) W63(-15.112,-1.51) W64(-15.763,-1.51) W65(-16.413,-1.51) W66(-17.063,-1.51) W67(-17.713,-1.51) W68(-18.364,-1.51) W69(-19.014,-1.51) W70(-19.664,-1.51) W71(-20.314,-1.51) Y15(12.188,-0.847) Y16(11.538,-0.847) Y17(10.888,-0.847) Y18(10.237,-0.847) Y19(9.587,-0.847) Y20(8.937,-0.847) Y21(8.287,-0.847) Y62(-14.644,-1.053)
  oval 0.254x0.343 smd: A6(17.467,-10.989) A7(16.791,-11.314) A9(15.664,-11.314) A10(14.989,-10.989) A11(14.313,-11.314) A13(13.186,-11.314) A14(12.511,-10.989) A15(11.835,-11.314) A17(10.708,-11.314) A18(10.033,-10.989) A19(9.357,-11.314) A21(8.23,-11.314) A22(7.555,-10.989) A23(6.879,-11.314) A25(5.752,-11.314) A26(5.077,-10.989) A27(4.401,-11.314) A29(3.274,-11.314) A30(2.599,-10.989) A31(1.923,-11.314) A33(0.796,-11.314) A34(0.121,-10.989) A36(-0.555,-11.314) A38(-1.682,-11.314) A39(-2.357,-10.989) A40(-3.033,-11.314) A42(-4.16,-11.314) A44(-4.835,-10.989) A45(-5.511,-11.314) A47(-6.638,-11.314) A48(-7.313,-10.989) A50(-7.989,-11.314) A52(-9.116,-11.314) A53(-9.791,-10.989) A54(-10.467,-11.314) A56(-11.594,-11.314) A58(-12.269,-10.989) A59(-12.945,-11.314) A61(-14.072,-11.314) A62(-14.747,-10.989) A63(-15.423,-11.314) A65(-16.55,-11.314) A66(-17.226,-10.989) A67(-17.901,-11.314) AY7(16.551,10.014) AY9(15.416,10.014) AY11(14.131,10.014) AY13(12.995,10.014) AY15(11.71,10.014) AY17(10.575,10.014) AY20(9.289,10.014) AY22(8.154,10.014) AY25(6.828,10.014) AY31(3.148,10.014) AY33(1.847,10.014) AY39(-1.833,10.014) AY42(-3.108,10.014) AY48(-6.789,10.014) AY50(-7.922,10.014) AY56(-11.602,10.014) AY59(-12.877,10.014) AY65(-16.558,10.014) AY67(-17.901,10.014) B7(16.791,-10.664) B9(15.664,-10.664) B11(14.313,-10.664) B13(13.186,-10.664) B15(11.835,-10.664) B17(10.708,-10.664) B19(9.357,-10.664) B21(8.23,-10.664) B23(6.879,-10.664) B25(5.752,-10.664) B27(4.401,-10.664) B29(3.274,-10.664) B31(1.923,-10.664) B33(0.796,-10.664) B36(-0.555,-10.664) B38(-1.682,-10.664) B40(-3.033,-10.664) B42(-4.16,-10.664) B45(-5.511,-10.664) B47(-6.638,-10.664) B50(-7.989,-10.664) B52(-9.116,-10.664) B54(-10.467,-10.664) B56(-11.594,-10.664) B59(-12.945,-10.664) B61(-14.072,-10.664) B63(-15.423,-10.664) B65(-16.55,-10.664) B67(-17.901,-10.664) BA4(18.366,10.689) BA6(17.173,10.258) BA7(16.61,10.664) BA9(15.416,10.664) BA10(14.753,10.258) BA11(14.189,10.664) BA13(12.995,10.664) BA14(12.332,10.258) BA15(11.768,10.664) BA17(10.575,10.664) BA18(9.912,10.258) BA20(9.348,10.664) BA22(8.154,10.664) BA25(6.828,10.664) BA26(6.165,10.339) BA27(5.502,10.664) BA29(4.473,10.664) BA30(3.811,10.339) BA31(3.148,10.664) BA33(1.847,10.664) BA34(1.184,10.339) BA35(0.521,10.664) BA37(-0.507,10.664) BA38(-1.17,10.339) BA39(-1.833,10.664) BA42(-3.108,10.664) BA43(-3.771,10.339) BA44(-4.434,10.664) BA46(-5.463,10.664) BA47(-6.126,10.339) BA48(-6.789,10.664) BA50(-7.922,10.664) BA51(-8.585,10.339) BA52(-9.248,10.664) BA54(-10.276,10.664) BA55(-10.939,10.339) BA56(-11.602,10.664) BA59(-12.877,10.664) BA60(-13.54,10.339) BA61(-14.203,10.664) BA63(-15.232,10.664) BA64(-15.895,10.339) BA65(-16.558,10.664) BA66(-17.221,10.339) BA67(-17.901,10.664) BB5(17.786,11.314) BB6(17.173,10.989) BB7(16.61,11.314) BB9(15.416,11.314) BB10(14.753,10.989) BB11(14.189,11.314) BB13(12.995,11.314) BB14(12.332,10.989) BB15(11.768,11.314) BB17(10.575,11.314) BB18(9.912,10.989) BB20(9.348,11.314) BB22(8.154,11.314) BB23(7.466,10.908) BB25(6.828,11.314) BB26(6.165,10.989) BB27(5.502,11.314) BB29(4.473,11.314) BB30(3.811,10.989) BB31(3.148,11.314) BB32(2.485,10.908) BB33(1.847,11.314) BB34(1.184,10.989) BB35(0.521,11.314) BB37(-0.507,11.314) BB38(-1.17,10.989) BB39(-1.833,11.314) BB41(-2.471,10.908) BB42(-3.108,11.314) BB43(-3.771,10.989) BB44(-4.434,11.314) BB46(-5.463,11.314) BB47(-6.126,10.989) BB48(-6.789,11.314) BB50(-7.922,11.314) BB51(-8.585,10.989) BB52(-9.248,11.314) BB54(-10.276,11.314) BB55(-10.939,10.989) BB56(-11.602,11.314) BB57(-12.24,10.908) BB59(-12.877,11.314) BB60(-13.54,10.989) BB61(-14.203,11.314) BB63(-15.232,11.314) BB64(-15.895,10.989) BB65(-16.558,11.314) BB66(-17.221,10.989) BB67(-17.901,11.314)
  oval 0.343x0.254 smd: AA1(19.989,-0.511) AB1(20.314,0.152) AB2(19.664,0.152) AB3(19.014,0.152) AC1(19.989,0.815) AC2(19.339,0.815) AD1(20.314,1.478) AD2(19.664,1.478) AD3(19.014,1.478) AF1(19.989,2.141) AF70(-19.664,1.84) AF71(-20.314,1.84) AG1(20.314,2.804) AG2(19.664,2.804) AG3(19.014,2.804) AG70(-19.339,2.503) AG71(-19.989,2.503) AH1(19.989,3.467) AH2(19.339,3.467) AH68(-18.364,3.166) AH69(-19.014,3.166) AH70(-19.664,3.166) AH71(-20.314,3.166) AJ1(20.314,4.13) AJ2(19.664,4.13) AJ3(19.014,4.13) AK70(-19.989,3.829) AL1(19.989,4.793) AL68(-18.364,4.492) AL69(-19.014,4.492) AL70(-19.664,4.492) AL71(-20.314,4.492) AM1(20.314,5.456) AM2(19.664,5.456) AM3(19.014,5.456) AM70(-19.339,5.155) AM71(-19.989,5.155) AN1(19.989,6.119) AN2(19.339,6.119) AN70(-19.664,5.818) AN71(-20.314,5.818) AP1(20.314,6.782) AP2(19.664,6.782) AP3(19.014,6.782) AR70(-19.664,6.846) AR71(-20.314,6.846) AT1(19.989,7.445) AT70(-19.339,7.509) AT71(-19.989,7.509) AU1(20.314,8.108) AU2(19.664,8.108) AU3(19.014,8.108) AU68(-18.364,8.147) AU69(-19.014,8.172) AU70(-19.664,8.172) AU71(-20.314,8.172) AV1(20.314,8.828) AV2(19.364,8.799) AV71(-20.314,8.901) AW2(19.689,9.362) AW3(19.039,9.362) E70(-19.664,-9.009) E71(-20.314,-8.901) F1(19.989,-8.466) F70(-19.212,-8.32) F71(-19.862,-8.384) G1(20.314,-7.803) G2(19.664,-7.803) G3(19.014,-7.803) G70(-19.664,-7.759) G71(-20.314,-7.759) H1(19.989,-7.14) H2(19.339,-7.14) H70(-19.339,-7.096) H71(-19.989,-7.096) J1(20.314,-6.477) J2(19.664,-6.477) J3(19.014,-6.477) J69(-19.014,-6.433) J70(-19.664,-6.433) J71(-20.314,-6.433) K71(-19.989,-5.744) L1(19.989,-5.814) M1(20.314,-5.151) M2(19.664,-5.151) M3(19.014,-5.151) N1(19.989,-4.488) N2(19.339,-4.488) P1(20.314,-3.825) P2(19.664,-3.825) P3(19.014,-3.825) T1(19.989,-3.162) U1(20.314,-2.499) U2(19.664,-2.499) U3(19.014,-2.499) V1(19.989,-1.836) V2(19.339,-1.836) W1(20.314,-1.173) W2(19.664,-1.173) W3(19.014,-1.173)
